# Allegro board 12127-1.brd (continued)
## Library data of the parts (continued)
C194 = C402H22: tolerance: 78.15322.2FL
C195 C3321 = C402H22: tolerance: 78.10521.5FL
C199 = C402H22: tolerance: 78.33224.2FL
C201 C204 C241 PC69 = C603H36: tolerance: 78.10422.2BL
C208 = C402H22: tolerance: 78.15134.1FL
C209 C3310-C3312 = C402H22: tolerance: 78.22321.2FL
C229 = C603H36: tolerance: 78.10523.2BL
C235 C236 C239 = C603: tolerance: 78.22224.2BL
C378 C379 = C402H24: tolerance: 78.12034.1FL
C383 = C402H22: tolerance: 78.47423.5FL; signal model: C402H20_SCD1U10V2KX-4GP
C423 = C603H36: tolerance: 78.12034.1BL
C443 = C603H36: tolerance: 78.15034.1BL
C467 C477 C518 C536 = C603H36: tolerance: 78.10613.5BL
C484 UC103 = C603H36: tolerance: 78.10523.5BL
C538 C539 = C402H22: tolerance: 78.10423.2FL; signal model: C402H22_SCD01U16V2KX-3GP
CMCLR1 MECLR1 PWCLR1 = 21S-91-03GB01: tolerance: 21.61445.103
D1 = SOT23-2D4-312H44: tolerance: 75.00054.I7D
D2 = SOD523AKH28: tolerance: 83.02015.0AF
D8 D18 = SOD323AKH38: tolerance: 83.00355.D1F
D21 D37 = SOD323AKH42: tolerance: 83.04148.D1H
D23 D26 = SOT23-2D4-312H48: tolerance: 75.00040.A7D
DB1 = G800W306018EU: tolerance: 21.61925.102
DIMM1 DIMM2 = 78079-0001: tolerance: 22.10244.D61
DQ61 Q12 Q44 Q45 Q53 Q57 Q59-Q61 Q70-Q72 Q74 Q79 Q109 Q110 = SOT23CBE2D4H44: tolerance: 84.T3904.C11
F5 F8 = POLYSW-4633-UH24: tolerance: 69.50007.B81
F6 F7 F9 F17 F18 = POLYSW-3217-UH40: tolerance: 69.50007.B91
FL1-FL5 L1 L2 L14-L16 L21 = L402H24: tolerance: 68.00213.031
FNCPU1 = HF08040-M1: tolerance: 21.60641.104
FVS1 = TPAD385X385: tolerance: ZZ.00PAD.Y31
G1 G2 G8-G11 = CON2C-U: tolerance: ZZ.CON2C.XXX
G3-G7 = GAP-CLOSE-PWR: tolerance: ZZ.CON2d.XXX
H1-H6 = GENS315R158-8-F-A: tolerance: ZZ.SCREW.541
H7 = STF256R107H132: tolerance: 34.3KF01.001
HDMI1 = G3168-18000101-00: tolerance: 62.10078.531
L3 R173 R178 R184-R187 R280 R281 R290 R532 R548 R567 = 0R0805-PAD: tolerance: ZZ.R0805.ZZZ
L4 = L201209H44: tolerance: 68.00029.191
L5-L7 L11-L13 L17 L20 = L1608-UH38: tolerance: 68.00217.361; signal model: L1608-UH38_FCM1608CF-750T2-GP
L8 = L603H38: tolerance: 68.00335.181
L18 L19 L22 L24 L32 L51 = L125100-4P-3H27: tolerance: 68.01210.20I
L23 = L3330-1230H95: tolerance: 68.4R710.20S
L27 L39 L40 = RT-D6-4D5-1010H375: tolerance: 19.40346.101
L44 = L603H38: tolerance: 68.00909.101
L45 = RT-D6D5-13H414-U: tolerance: 19.40364.001
L50 = RT-D6D2-108108H426: tolerance: 19.40346.051
LED1 = 19-21UBC-1: tolerance: 83.01921.C70
LEDH1 = 14452190: tolerance: 21.62711.206
LPC1 = A2005WV0-2DX7P-6T-2D3: tolerance: 21.61154.207
MINI1 = 80051-6021: tolerance: 20.F1692.052
PC73 = C603: tolerance: 78.15224.2BL
PR83 PR110 PR111 PR127 R87 R182 R248 R259 R266 R267 R270 R293 = R805H24: tolerance: 63.2R231.16L
PR84 = R402H16: tolerance: 64.47035.6DL
PR85 R79 R209 R241 R254-R256 R283 R302 R682 R684 R693 R703 R729 R738 = R402H16: tolerance: 64.10025.6DL
PR86 R200 R229 R243 R305 R429 R472 R677 R678 R681 R689-R692 R699 R705 = R402H16: tolerance: 63.R0034.1DL
PR87 = R402H16: tolerance: 64.11525.6DL
PR106 PR134 R41 R106 R114 R115 R240 = R402H16: tolerance: 64.10035.6DL
PR109 PR126 R24 R140 R181 R193 R197 R312 R351 R367 R388 R395 R398 R402 R403 R405 R410 R414 R415 R418-R420 R422 R427 R439 R441 R442 R445 R455 R464-R467 R485 R486 R491 R508 R524 R534 R536 R556 R560 R562-R566 R570 R571 R573 R574 R580 R583-R585 R590 R593-R597 R602 R605-R607 R609 R613 R615 R616 R619-R621 R623 R625 R634 R636 R642 R647 R648 R650 R651 R658 R659 R662 R669 R670 R672 R676 R679 R683 R685 R687 R688 R698 R707 R712 R713 R755 R762 R776-R778 R788 R789 R791 R794 R795 R2239 UR98-UR100 UR118 = R402H16: tolerance: 63.10334.1DL
PU8 = DFN10G3-G265175H32: tolerance: 74.08237.B73
Q4 Q5 Q58 Q77 Q78 Q80 = SOT23DGS2D4H44: tolerance: 84.2N702.031
Q6 Q39 Q46 Q47 = SOT23DGS2D8H50: tolerance: 84.03413.A31
Q9-Q11 Q14 Q17 = SOT23-2D4-312H46: tolerance: 75.05125.07D
Q13 Q16 Q26 Q27 Q31 Q32 Q34 = PPAK-5PH45: tolerance: 84.00172.A37
Q15 Q22 Q23 Q28-Q30 Q35 Q43 = PPAK-5PH45: tolerance: 84.SRA12.037
Q37 Q40 Q42 Q48-Q50 Q55 Q62 Q64 Q67 QF2 = SOT-363H44: tolerance: 75.03904.B7C
Q38 = SOT23DGS2D4H44: tolerance: 84.2N702.J31
Q51 = SMD-TO-252-DGS6698H99: tolerance: 84.03006.036
Q54 Q56 = SOT23DGS2D4H44: tolerance: 84.27002.W31
Q69 Q73 U3 U4 U53 = SOT-363H44: tolerance: 75.27002.B7C
Q82 = SOT23CBE2D4H44: tolerance: 84.T3906.A11
Q89 Q90 = SOT23DGS2D8H50: tolerance: 84.03401.B31
Q108 = SOT-363H44: tolerance: 84.M3904.B1F
R3 R4 R21 R70 R82 R84 R88 R144 R257 R392 R411 R413 R423 R456-R458 R469 R476 R477 R484 R504 R507 R514 R519 R525 R538 R577 R598 R599 R601 R618 R624 R627 R630 R631 R635 R646 R649 R655 R656 R660 R696 R701 R717 R737 R754 R756 R757 R767 R773 R790 R792 R810 R826-R846 R848 R849 R865 R867 = R402H16: tolerance: 63.10234.1DL
R5 R12 R20 R67 R68 R356 R404 R459 R481 R499 R765 = R402H16: tolerance: 64.20025.6DL
R6 R7 R43 R44 R77 R90 R92 R130 R495 R2220 = R402H16: tolerance: 63.22334.1DL
R8 R261 R2240 = R402H16: tolerance: 64.39225.6DL
R9 R10 R15-R18 R45 R50 R51 R65 R66 R183 R362 R526 R535 R546 = R402H16: tolerance: 63.22234.1DL
R11 R110 R117 R282 R284 = 0R0603-PAD-1: tolerance: ZZ.00PAD.M21
R13 R14 R111 R119 R541 R680 R764 R796 R812 R818 R2219 = R402H14: tolerance: 64.10005.6DL
R19 R710 = R402H16: tolerance: 64.20015.6DL
R25 R73 R2234-R2236 = R402H16: tolerance: 63.51234.1DL
R26 R48 R52 R53 R76 R91 R417 R424 = R402H16: tolerance: 64.75R05.6DL
R27 R49 R72 R83 R107 R352 R438 R470 R492 R498 R604 R638 R671 R709 R727 R736 R760 R2237 = R402H16: tolerance: 63.47234.1DL
R29 R69 R171 = R603H22: tolerance: 63.00000.00L
R30-R32 R159 R412 R425 R426 = R402H16: tolerance: 64.15005.6DL
R33 R34 = R402H16: tolerance: 64.49905.6DL
R57-R64 = R402H16: tolerance: 63.47134.1DL
R71 R112 R124 R132 R139 R198 R242 R258 R269 R304 R311 R333 R497 R552 R578 R579 R667 R673 R759 R806-R808 R823 R824 R847 R1248 = R402H16: tolerance: 63.R0034.1DL; signal model: R402H16_0R2J-2-GP
R74 R478 R488 R505 R512 R542 R610 R612 R629 R632 R652 R850 R852 = R402H16: tolerance: 63.33034.1DL
R75 R118 = R402H16: tolerance: 64.47R05.6DL
R78 R298 R299 R502 = R402H16: tolerance: 63.10534.1DL
R80 R97 R99 R104 R409 = 0R0603-PAD: tolerance: ZZ.R0603.001
R93-R95 = R402H16: tolerance: 64.12035.6DL
R96 R98 R100 R287 = R402H14: tolerance: 64.10R05.6DL
R102 R800 = R402H16: tolerance: 64.11005.6DL
R103 = R402H16: tolerance: 64.18025.6DL
R105 = R402H16: tolerance: 64.56225.6DL
R108 R401 = R402H16: tolerance: 63.10434.1DL
R109 = R402H16: tolerance: 64.51R15.6DL
R113 = R402H16: tolerance: 64.75025.6DL
R116 R233 R286 R288 R518 R664 R665 R704 R769 R853 R857 R859 = R402H16: tolerance: 64.10015.6DL
R120 = NTC-402H24: tolerance: 69.60028.031
R126 = R402H16: tolerance: 64.47R55.6DL
R127-R129 R136 R138 R264 R416 R533 R561 R581 R637 R702 R708 R761 R819-R821 = 0R0402-PAD: tolerance: ZZ.R0402.001; signal model: R402H16_0R2J-2-GP
R131 = R402H16: tolerance: 63.10334.1DL; signal model: R402H16_0R2J-2-GP
R133 R358 R368 R369 R399 R468 R471 R643 R751 R752 R2243 = R402H16: tolerance: 64.82015.6DL
R134 = R402H16: tolerance: 63.82234.1DL
R145 R428 R723 UC97 UR106 UR107 UR119 = R402H16: tolerance: 63.15334.1DL
R150 R391 R851 R854 R858 = 0R0402-PAD: tolerance: ZZ.R0402.001
R153 R396 R406-R408 R421 = R402H16: tolerance: 63.22034.1DL
R156 R177 R203 R340 R639 R640 R661 R663 R816 R2216 = R402H16: tolerance: 64.51R05.6DL
R162 R430 = R603H22: tolerance: 64.10045.55L
R163-R165 = R402H16: tolerance: 64.68015.6DL
R172 = R402H16: tolerance: 64.24915.6DL
R180 R190 R195 R196 R245 R268 = R805H24: tolerance: 63.1R031.16L
R207 = NTC-603H28: tolerance: 69.60026.091
R212 R400 = R402H16: tolerance: 64.39015.6DL
R219 = R402H16: tolerance: 64.20525.6DL
R220 = R402H16: tolerance: 64.56035.6DL
R221 = R402H16: tolerance: 64.69825.6DL
R222 = R402H16: tolerance: 64.88715.6DL
R225 = R402H16: tolerance: 64.59025.6DL
R226 = R402H16: tolerance: 64.54R95.6DL
R231 = R402H16: tolerance: 64.31625.6DL
R235 = R402H16: tolerance: 64.19635.6DL
R239 = R402H16: tolerance: 64.68025.6DL
R251 = R805H24: tolerance: 63.10133.16L
R263 = R402H16: tolerance: 63.56034.1DL
R265 R855 R863 = R402H16: tolerance: 64.2R005.6DL
R277 R2226 = R402H16: tolerance: 64.33015.6DL
R279 = R402H16: tolerance: 64.12425.6DL
R307 R793 R805 R856 R864 = R402H16: tolerance: 64.24R95.6DL
R341 R360 R554 = R402H14: tolerance: 63.10134.1DL
R353 R482 = R402H16: tolerance: 64.90R95.6DL
R357 R483 R489 R493 R496 R521 R523 R866 = 0R0402-PAD-1: tolerance: ZZ.00PAD.M11
R393 = R402H16: tolerance: 64.64905.6DL
R494 R515 = R402H16: tolerance: 63.39434.1DL
R516 = R402H16: tolerance: 64.44R25.6DL
R537 = R402H16: tolerance: 64.12405.6DL
R547 R576 R694 R695 R697 = R402H16: tolerance: 64.75015.6DLDL
R549 R644 R734 = R805H24: tolerance: 63.22133.16L
R550 R551 R555 = R805H24: tolerance: 63.R0031.16L
R553 = R603H22: tolerance: 63.10633.15L
R559 = R402H16: tolerance: 64.21005.6DL
R568 R600 R666 R674 R720 R733 R774 R775 SR732 = 0R0402-PAD: tolerance: ZZ.R0402.ZZZ
R572 R668 = R402H16: tolerance: 63.20334.1DL
R617 = R402H16: tolerance: 64.22R65.6DL
R633 R641 R657 = R402H16: tolerance: 63.68134.1DL
R653 R654 = R603H22: tolerance: 63.75033.15L
R711 = R402H16: tolerance: 64.21015.6DL
R722 = R603H22: tolerance: 63.10233.15L
R730 R768 = R402H16: tolerance: 63.27234.1DL
R739 = R402H16: tolerance: 64.49915.6DL
R747 = R402H16: tolerance: 63.56234.1DL
R766 R811 R817 = R402H16: tolerance: 64.20005.6DL
R772 = 0R0805-PAD: tolerance: ZZ.R0805.001
R797-R799 R804 = R402H16: tolerance: 64.49R95.6DL
R1549 = R402H16: tolerance: 63.47334.1DL
R2215 = R402H16: tolerance: 64.15015.6DL
R2217 = R402H16: tolerance: 64.82505.6DL
R2218 UR108 UR109 = R402H16: tolerance: 64.24905.6DL
R2225 = R402H16: tolerance: 64.5R115.6DL
R2227 = R402H16: tolerance: 64.18015.6DL
R2230 = R402H16: tolerance: 64.60415.6DL
R2231 = R402H16: tolerance: 64.26715.6DL
R2233 = R402H16: tolerance: 64.11825.6DL
R2238 = R402H16: tolerance: 63.30334.1DL
R2246 = R603H22: tolerance: 63.2R233.15L
RJ45 = RU4-161A9WGF: tolerance: 22.10321.K21
RN2 RN3 RN7 = ARES8-CN24H20: tolerance: 66.82236.A8L
RN22 = SMD-ARES4H18: tolerance: 66.10236.04L
RN31-RN36 RN40-RN42 RN64 RN66 = ARES2H18: tolerance: 66.10336.04L
RN46 = ARES8-CN24-UH20: tolerance: 66.33036.A8L
RN57 RN58 RN60 RN62 = SMD-ARES4H18: tolerance: 66.33036.04L
RN65 = SMD-ARES4: tolerance: 66.82236.04L
SATA0 = ABA-SAT-010-K50: tolerance: 20.81696.007
SATA1 = ABA-SAT-010-K04-U: tolerance: 20.81274.007
SLOT1 = 1-1470780-7: tolerance: 20.50222.036
SLOT2 = 4-1470780-7: tolerance: 20.50232.164
TC1-TC3 TC10 TC12 TC29 TC41 = ECAP-100D6D3H375: tolerance: 09.56710.A8L
TC4-TC7 = ECAP-100D6D3H237: tolerance: 09.1071D.2AL
TC9 TC34 TC40 = ECAP-138D8-UH355: tolerance: 09.2771D.C8L
TC11 = ECAP-138D8H512: tolerance: 09.4771D.L16
TC13 = ECAP-80D5H493: tolerance: 09.1071D.A89
TC15 TC22 TC42 TC45 = ECAP-100D6D3H375: tolerance: 09.8271V.08L
TC38 UTC5-UTC7 UTC9 = ECAP-100D6D3H473: tolerance: 09.2271D.X8L
TP1 TP3-TP7 TP10 TP32-TP36 TP40-TP42 TP48-TP51 TP53 TP56 TP66-TP68 TP76-TP80 TP85 TP86 TP88 TP90 = TPAD24: tolerance: ZZ.PAD24.001
TP2 TP87 TP103-TP105 TP107-TP113 TP116-TP131 TP133-TP169 = TPAD28: tolerance: ZZ.PAD28.XXX
TR1-TR4 = L2012-4P-MH56: tolerance: 69.10171.001
TR9-TR14 TR18-TR20 TR22-TR27 = L125100-4P-1H37: tolerance: 68.01012.201
U1 U6 U9 U11 U24 U26 UU12 UU37 UU38 UU42 UU43 = SOT-6H58: tolerance: 75.09904.07C
U2 = LQFP48H63: tolerance: 71.00662.A0G
U8 U16 U18 = DFN8G2-G1309-UH40: tolerance: 74.81161.073
U10 U15 U47 = SLP2510P8-1H22: tolerance: 83.03010.0A0
U12 = QFN32J4-G2D9-U1H36: tolerance: 71.08111.U03
U13 = SOIC8-G3530H63: tolerance: 74.05337.031
U14 U31 = SOIC8H79: tolerance: 84.02402.037
U17 = SOT-6H58: tolerance: 74.05611.03P
U22 = TSOIC28-3H44: tolerance: 71.08172.00W
U23 = TSOIC28H48: tolerance: 71.03324.H0W
U25 U32 U34 = DFN10G2510H26: tolerance: 83.01045.AA0
U27 = SKTBGA1150R740611UH367NF: tolerance: 62.10055.741
U29 = BGA708Z2322H65: tolerance: 71.0LYNX.B0U
U30CN1 U35CN1 = ACA-SPI-004-K-U: tolerance: 62.10089.001
U33 U39 = SOIC8-1H86: tolerance: 72.25640.D01
U36 = SMD-TO-252-4H94: tolerance: 74.01085.P3M
U51 = SOIC8-G3530H63: tolerance: 74.05930.B3D
U52 = QFN32J4-G2D8-3H40: tolerance: 74.81102.C73
U61 = LQFP64H63: tolerance: 71.08772.B0G
UR112 = R402H16: tolerance: 63.33134.1DL
USB3R1 = SKT-USB22-156174: tolerance: 22.10339.641
USBCN1 = SKT-USB12-157183: tolerance: 22.10321.W41
USBF1 USBF2 = 210-92-05GB04: tolerance: 21.62876.205
USBF3 = ABA-USB-050-K07: tolerance: 22.10341.131
VGA1 = DZ11AA1-H5W7-4F: tolerance: 20.20503.015
X1 X2 = SMD49-4H56: tolerance: 82.30020.851
X3 = SMD49-6914-0403H56: tolerance: 82.30001.841
XDPC1 = BSH-03001-FDA: tolerance: 20.F0441.060

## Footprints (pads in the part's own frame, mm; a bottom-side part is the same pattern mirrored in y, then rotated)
0R0402-PAD
  custom 0.14x0.14 smd: 1(0,0.445) 2(0,-0.445)
0R0402-PAD-1
  custom 0.14x0.14 smd: 1(0,0.445) 2(0,-0.445)
0R0603-PAD
  custom 0.216x0.216 smd: 1(0,0.851) 2(0,-0.673)
0R0603-PAD-1
  custom 0.216x0.216 smd: 1(0,0.851) 2(0,-0.673)
0R0805-PAD
  rect 1.397x1.562 smd: 1(0,0.965)
  rect 1.397x1.569 smd: 2(0,-0.965)
1-1470780-7
  round 0.254 hole 2.362 unplated: (0,0) (9.149,0)
  round 1.092 hole 0.737: A1(-11.651,1.25) A2(-10.65,3.25) A3(-9.651,1.25) A4(-8.65,3.25) A5(-7.65,1.25) A6(-6.651,3.25) A7(-5.65,1.25) A8(-4.651,3.25) A9(-3.65,1.25) A10(-2.65,3.25) A11(-1.651,1.25) A12(1.35,3.25) A13(2.349,1.25) A14(3.349,3.25) A15(4.35,1.25) A16(5.349,3.25) A17(6.35,1.25) A18(7.349,3.25) B1(-11.651,-1.25) B2(-10.65,-3.25) B3(-9.651,-1.25) B4(-8.65,-3.25) B5(-7.65,-1.25) B6(-6.651,-3.25) B7(-5.65,-1.25) B8(-4.651,-3.25) B9(-3.65,-1.25) B10(-2.65,-3.25) B11(-1.651,-1.25) B12(1.35,-3.25) B13(2.349,-1.25) B14(3.349,-3.25) B15(4.35,-1.25) B16(5.349,-3.25) B17(6.35,-1.25) B18(7.349,-3.25)
1-1775099-0
  round 2.159 hole 1.397: 1(-2.101,2.75) 2(2.101,2.75) 3(-2.101,-2.75) 4(2.101,-2.75)
4-1470780-7
  round 0.254 hole 2.362 unplated: (0,0) (73.149,0)
  round 1.092 hole 0.737: A1(-11.65,1.25) A2(-10.65,3.25) A3(-9.649,1.25) A4(-8.65,3.25) A5(-7.65,1.25) A6(-6.65,3.25) A7(-5.65,1.25) A8(-4.649,3.25) A9(-3.65,1.25) A10(-2.65,3.25) A11(-1.65,1.25) A12(1.35,3.25) A13(2.349,1.25) A14(3.35,3.25) A15(4.35,1.25) A16(5.351,3.25) A17(6.35,1.25) A18(7.349,3.25) A19(8.35,1.25) A20(9.35,3.25) A21(10.351,1.25) A22(11.35,3.25) A23(12.349,1.25) A24(13.35,3.25) A25(14.35,1.25) A26(15.35,3.25) A27(16.35,1.25) A28(17.349,3.25) A29(18.35,1.25) A30(19.35,3.25) A31(20.35,1.25) A32(21.35,3.25) A33(22.349,1.25) A34(23.35,3.25) A35(24.35,1.25) A36(25.35,3.25) A37(26.35,1.25) A38(27.349,3.25) A39(28.35,1.25) A40(29.35,3.25) A41(30.35,1.25) A42(31.35,3.25) A43(32.349,1.25) A44(33.35,3.25) A45(34.35,1.25) A46(35.35,3.25) A47(36.35,1.25) A48(37.349,3.25) A49(38.35,1.25) A50(39.35,3.25) A51(40.35,1.25) A52(41.35,3.25) A53(42.349,1.25) A54(43.35,3.25) A55(44.35,1.25) A56(45.35,3.25) A57(46.35,1.25) A58(47.349,3.25) A59(48.35,1.25) A60(49.35,3.25) A61(50.35,1.25) A62(51.35,3.25) A63(52.349,1.25) A64(53.35,3.25) A65(54.35,1.25) A66(55.35,3.25) A67(56.35,1.25) A68(57.349,3.25) A69(58.35,1.25) A70(59.35,3.25) A71(60.35,1.25) A72(61.35,3.25) A73(62.349,1.25) A74(63.35,3.25) A75(64.35,1.25) A76(65.35,3.25) A77(66.35,1.25) A78(67.349,3.25) A79(68.35,1.25) A80(69.35,3.25) A81(70.35,1.25) A82(71.35,3.25) B1(-11.65,-1.25) B2(-10.65,-3.25) B3(-9.649,-1.25) B4(-8.65,-3.25) B5(-7.65,-1.25) B6(-6.65,-3.25) B7(-5.65,-1.25) B8(-4.649,-3.25) B9(-3.65,-1.25) B10(-2.65,-3.25) B11(-1.65,-1.25) B12(1.35,-3.25) B13(2.349,-1.25) B14(3.35,-3.25) B15(4.35,-1.25) B16(5.351,-3.25) B17(6.35,-1.25) B18(7.349,-3.25) B19(8.35,-1.25) B20(9.35,-3.25) B21(10.351,-1.25) B22(11.35,-3.25) B23(12.349,-1.25) B24(13.35,-3.25) B25(14.35,-1.25) B26(15.35,-3.25) B27(16.35,-1.25) B28(17.349,-3.25) B29(18.35,-1.25) B30(19.35,-3.25) B31(20.35,-1.25) B32(21.35,-3.25) B33(22.349,-1.25) B34(23.35,-3.25) B35(24.35,-1.25) B36(25.35,-3.25) B37(26.35,-1.25) B38(27.349,-3.25) B39(28.35,-1.25) B40(29.35,-3.25) B41(30.35,-1.25) B42(31.35,-3.25) B43(32.349,-1.25) B44(33.35,-3.25) B45(34.35,-1.25) B46(35.35,-3.25) B47(36.35,-1.25) B48(37.349,-3.25) B49(38.35,-1.25) B50(39.35,-3.25) B51(40.35,-1.25) B52(41.35,-3.25) B53(42.349,-1.25) B54(43.35,-3.25) B55(44.35,-1.25) B56(45.35,-3.25) B57(46.35,-1.25) B58(47.349,-3.25) B59(48.35,-1.25) B60(49.35,-3.25) B61(50.35,-1.25) B62(51.35,-3.25) B63(52.349,-1.25) B64(53.35,-3.25) B65(54.35,-1.25) B66(55.35,-3.25) B67(56.35,-1.25) B68(57.349,-3.25) B69(58.35,-1.25) B70(59.35,-3.25) B71(60.35,-1.25) B72(61.35,-3.25) B73(62.349,-1.25) B74(63.35,-3.25) B75(64.35,-1.25) B76(65.35,-3.25) B77(66.35,-1.25) B78(67.349,-3.25) B79(68.35,-1.25) B80(69.35,-3.25) B81(70.35,-1.25) B82(71.35,-3.25)
19-21UBC-1
  rect 0.94x1.067 smd: 1(-0.711,0) 2(0.711,0)
21S-91-03GB01
  round 1.422 hole 1.016: 1(-2.54,0) 2(0,0) 3(2.54,0)
210-92-05GB04
  round 1.422 hole 1.016: 1(-5.08,-1.27) 2(-5.08,1.27) 3(-2.54,-1.27) 4(-2.54,1.27) 5(0,-1.27) 6(0,1.27) 7(2.54,-1.27) 8(2.54,1.27) 10(5.08,1.27)
  rect 0.025x0.025 smd: 9(5.08,-1.27)
78079-0001
  round 0.254 hole 2.464 unplated: (-57,0) (81,0)
  round 0.254 hole 2.464x1.803 unplated: (0,0)
  round 1.092 hole 0.737: 1(-49.5,-0.95) 2(-48.5,-2.85) 3(-47.5,-0.95) 4(-46.5,-2.85) 5(-45.5,-0.95) 6(-44.5,-2.85) 7(-43.5,-0.95) 8(-42.5,-2.85) 9(-41.5,-0.95) 10(-40.5,-2.85) 11(-39.5,-0.95) 12(-38.5,-2.85) 13(-37.5,-0.95) 14(-36.5,-2.85) 15(-35.5,-0.95) 16(-34.5,-2.85) 17(-33.5,-0.95) 18(-32.5,-2.85) 19(-31.5,-0.95) 20(-30.5,-2.85) 21(-29.5,-0.95) 22(-28.5,-2.85) 23(-27.5,-0.95) 24(-26.5,-2.85) 25(-25.5,-0.95) 26(-24.5,-2.85) 27(-23.5,-0.95) 28(-22.5,-2.85) 29(-21.5,-0.95) 30(-20.5,-2.85) 31(-19.5,-0.95) 32(-18.5,-2.85) 33(-17.5,-0.95) 34(-16.5,-2.85) 35(-15.5,-0.95) 36(-14.5,-2.85) 37(-13.5,-0.95) 38(-12.5,-2.85) 39(-11.5,-0.95) 40(-10.5,-2.85) 41(-9.5,-0.95) 42(-8.5,-2.85) 43(-7.5,-0.95) 44(-6.5,-2.85) 45(-5.5,-0.95) 46(-4.5,-2.85) 47(-3.5,-0.95) 48(-2.5,-2.85) 49(2.5,-0.95) 50(3.5,-2.85) 51(4.5,-0.95) 52(5.5,-2.85) 53(6.5,-0.95) 54(7.5,-2.85) 55(8.5,-0.95) 56(9.5,-2.85) 57(10.5,-0.95) 58(11.5,-2.85) 59(12.5,-0.95) 60(13.5,-2.85) 61(14.5,-0.95) 62(15.5,-2.85) 63(16.5,-0.95) 64(17.5,-2.85) 65(18.5,-0.95) 66(19.5,-2.85) 67(20.5,-0.95) 68(21.5,-2.85) 69(22.5,-0.95) 70(23.5,-2.85) 71(24.5,-0.95) 72(25.5,-2.85) 73(26.5,-0.95) 74(27.5,-2.85) 75(28.5,-0.95) 76(29.5,-2.85) 77(30.5,-0.95) 78(31.5,-2.85) 79(32.5,-0.95) 80(33.5,-2.85) 81(34.5,-0.95) 82(35.5,-2.85) 83(36.5,-0.95) 84(37.5,-2.85) 85(38.5,-0.95) 86(39.5,-2.85) 87(40.5,-0.95) 88(41.5,-2.85) 89(42.5,-0.95) 90(43.5,-2.85) 91(44.5,-0.95) 92(45.5,-2.85) 93(46.5,-0.95) 94(47.5,-2.85) 95(48.5,-0.95) 96(49.5,-2.85) 97(50.5,-0.95) 98(51.5,-2.85) 99(52.5,-0.95) 100(53.5,-2.85) 101(54.5,-0.95) 102(55.5,-2.85) 103(56.5,-0.95) 104(57.5,-2.85) 105(58.5,-0.95) 106(59.5,-2.85) 107(60.5,-0.95) 108(61.5,-2.85) 109(62.5,-0.95) 110(63.5,-2.85) 111(64.5,-0.95) 112(65.5,-2.85) 113(66.5,-0.95) 114(67.5,-2.85) 115(68.5,-0.95) 116(69.5,-2.85) 117(70.5,-0.95) 118(71.5,-2.85) 119(72.5,-0.95) 120(73.5,-2.85) 121(-49.5,2.85) 122(-48.5,0.95) 123(-47.5,2.85) 124(-46.5,0.95) 125(-45.5,2.85) 126(-44.5,0.95) 127(-43.5,2.85) 128(-42.5,0.95) 129(-41.5,2.85) 130(-40.5,0.95) 131(-39.5,2.85) 132(-38.5,0.95) 133(-37.5,2.85) 134(-36.5,0.95) 135(-35.5,2.85) 136(-34.5,0.95) 137(-33.5,2.85) 138(-32.5,0.95) 139(-31.5,2.85) 140(-30.5,0.95) 141(-29.5,2.85) 142(-28.5,0.95) 143(-27.5,2.85) 144(-26.5,0.95) 145(-25.5,2.85) 146(-24.5,0.95) 147(-23.5,2.85) 148(-22.5,0.95) 149(-21.5,2.85) 150(-20.5,0.95) 151(-19.5,2.85) 152(-18.5,0.95) 153(-17.5,2.85) 154(-16.5,0.95) 155(-15.5,2.85) 156(-14.5,0.95) 157(-13.5,2.85) 158(-12.5,0.95) 159(-11.5,2.85) 160(-10.5,0.95) 161(-9.5,2.85) 162(-8.5,0.95) 163(-7.5,2.85) 164(-6.5,0.95) 165(-5.5,2.85) 166(-4.5,0.95) 167(-3.5,2.85) 168(-2.5,0.95) 169(2.5,2.85) 170(3.5,0.95) 171(4.5,2.85) 172(5.5,0.95) 173(6.5,2.85) 174(7.5,0.95) 175(8.5,2.85) 176(9.5,0.95) 177(10.5,2.85) 178(11.5,0.95) 179(12.5,2.85) 180(13.5,0.95) 181(14.5,2.85) 182(15.5,0.95) 183(16.5,2.85) 184(17.5,0.95) 185(18.5,2.85) 186(19.5,0.95) 187(20.5,2.85) 188(21.5,0.95) 189(22.5,2.85) 190(23.5,0.95) 191(24.5,2.85) 192(25.5,0.95) 193(26.5,2.85) 194(27.5,0.95) 195(28.5,2.85) 196(29.5,0.95) 197(30.5,2.85) 198(31.5,0.95) 199(32.5,2.85) 200(33.5,0.95) 201(34.5,2.85) 202(35.5,0.95) 203(36.5,2.85) 204(37.5,0.95) 205(38.5,2.85) 206(39.5,0.95) 207(40.5,2.85) 208(41.5,0.95) 209(42.5,2.85) 210(43.5,0.95) 211(44.5,2.85) 212(45.5,0.95) 213(46.5,2.85) 214(47.5,0.95) 215(48.5,2.85) 216(49.5,0.95) 217(50.5,2.85) 218(51.5,0.95) 219(52.5,2.85) 220(53.5,0.95) 221(54.5,2.85) 222(55.5,0.95) 223(56.5,2.85) 224(57.5,0.95) 225(58.5,2.85) 226(59.5,0.95) 227(60.5,2.85) 228(61.5,0.95) 229(62.5,2.85) 230(63.5,0.95) 231(64.5,2.85) 232(65.5,0.95) 233(66.5,2.85) 234(67.5,0.95) 235(68.5,2.85) 236(69.5,0.95) 237(70.5,2.85) 238(71.5,0.95) 239(72.5,2.85) 240(73.5,0.95)
80051-6021
  round 0.254 hole 1.575 unplated: (-12.5,0)
  round 0.254 hole 1.067 unplated: (12.5,0)
  rect 0.559x2.007 smd: 1(-11.8,-4.097) 2(-11.4,4.097) 3(-11,-4.097) 4(-10.6,4.097) 5(-10.2,-4.097) 6(-9.8,4.1) 7(-9.4,-4.097) 8(-9,4.097) 9(-8.6,-4.097) 10(-8.2,4.097) 11(-7.8,-4.097) 12(-7.4,4.097) 13(-7,-4.097) 14(-6.6,4.097) 15(-6.2,-4.097) 16(-5.8,4.097) 17(-2.2,-4.097) 18(-1.8,4.097) 19(-1.4,-4.097) 20(-1,4.097) 21(-0.6,-4.097) 22(-0.2,4.097) 23(0.2,-4.097) 24(0.6,4.097) 25(1,-4.097) 26(1.4,4.097) 27(1.8,-4.097) 28(2.2,4.097) 29(2.6,-4.097) 30(3,4.097) 31(3.4,-4.097) 32(3.8,4.097) 33(4.2,-4.097) 34(4.6,4.097) 35(5,-4.097) 36(5.4,4.097) 37(5.8,-4.097) 38(6.2,4.097) 39(6.6,-4.097) 40(7,4.097) 41(7.4,-4.097) 42(7.8,4.097) 43(8.2,-4.097) 44(8.6,4.097) 45(9,-4.097) 46(9.4,4.097) 47(9.8,-4.097) 48(10.2,4.097) 49(10.6,-4.097) 50(11,4.097) 51(11.4,-4.097) 52(11.8,4.097)
  rect 2.311x3.2 smd: 53(-14.65,-3.5) 54(14.65,-3.5)
14452190
  round 1.397 hole 0.991: 1(6.35,1.27) 2(6.35,-1.27) 3(3.81,1.27) 4(3.81,-1.27) 5(1.27,1.27) 6(1.27,-1.27) 7(-1.27,1.27) 8(-1.27,-1.27) 9(-3.81,1.27) 11(-6.35,1.27) 12(-6.35,-1.27)
  rect 0.025x0.025 smd: 10(-3.81,-1.27)
A2005WV0-2DX7P-6T-2D3
  round 1.27 hole 0.889: 1(-6,-1) 2(-6,1) 3(-4,-1) 4(-4,1) 5(-2,-1) 6(-2,1) 7(0,-1) 8(0,1) 9(2,-1) 10(2,1) 11(4,-1) 12(4,1) 13(6,-1) 14(6,1)
AAA-BAT-029-P02
  round 1.524 hole 1.118: 1(12.29,0)
  round 1.422 hole 1.016: 2(-7.71,0)
ABA-JAK-028-K03
  round 0.254 hole 2.311 unplated: (0,0)
  round 1.422 hole 1.016: 1(0,-3.8) 2(-5,-3.8) 3(-2.5,-3.8) 4(2.5,-3.8) 5(5,-3.8) 22(-3.75,-8.8) 23(-1.25,-8.8) 24(1.25,-8.8) 25(3.75,-8.8) 32(-3.75,-13.8) 33(-1.25,-13.8) 34(1.25,-13.8) 35(3.75,-13.8)
  round 2.718 hole 2.311: G1(6.04,0) G2(-6.04,0) G3(6.04,-11.3) G4(-6.04,-11.3)
ABA-SAT-010-K04-U
  round 1.118 hole 0.762: 1(-3.81,-0.5) 4(0,-0.5) 7(3.81,-0.5)
  oval 1.041x1.168 hole 0.762: 2(-2.54,0.5) 3(-1.27,0.5) 5(1.27,0.5) 6(2.54,0.5)
  round 1.778 hole 1.372: 8(-6.48,0) 9(6.48,0)
ABA-SAT-010-K50
  round 1.118 hole 0.762: 1(3.81,-0.5) 4(0,-0.5) 7(-3.81,-0.5)
  oval 1.041x1.168 hole 0.762: 2(2.54,0.5) 3(1.27,0.5) 5(-1.27,0.5) 6(-2.54,0.5)
  round 1.778 hole 1.372: 8(6.48,0) 9(-6.48,0)
ABA-USB-050-K07
  round 1.168 hole 0.813: 1(-9,1) 2(-7,1) 3(-5,1) 4(-3,1) 5(-1,1) 6(1,1) 7(3,1) 8(5,1) 9(7,1) 10(9,1) 11(9,-1) 12(7,-1) 13(5,-1) 14(3,-1) 15(1,-1) 16(-1,-1) 17(-3,-1) 18(-5,-1) 19(-7,-1)
  rect 0.025x0.025 smd: 20(-9,-1)
ACA-SPI-004-K-U
  rect 0.508x1.499 smd: 1(1.905,4) 2(0.635,4) 3(-0.635,4) 4(-1.905,4) 5(-1.905,-4) 6(-0.635,-4) 7(0.635,-4) 8(1.905,-4)
ARES2H18
  rect 0.356x0.66 smd: 1(-0.325,-0.599) 2(0.325,-0.599) 3(0.325,0.599) 4(-0.325,0.599)
ARES8-CN24-UH20
  rect 0.61x0.66 smd: 1(-0.9,-0.486) 4(0.9,-0.486) 5(0.9,0.486) 8(-0.9,0.486)
  rect 0.305x0.66 smd: 2(-0.25,-0.486) 3(0.25,-0.486) 6(0.25,0.486) 7(-0.25,0.486)
ARES8-CN24H20
  rect 0.61x0.66 smd: 1(-0.9,-0.486) 4(0.9,-0.486) 5(0.9,0.486) 8(-0.9,0.486)
  rect 0.305x0.66 smd: 2(-0.25,-0.486) 3(0.25,-0.486) 6(0.25,0.486) 7(-0.25,0.486)
BGA708Z2322H65
  round 0.533 smd: A2(-10.171,10.299) A40(10.339,10.299) AV1(-10.799,-9.839) AV41(10.799,-9.839) AW2(-10.339,-10.299) AW40(10.339,-10.299) B1(-10.799,9.672) B41(10.799,9.839)
  round 0.406 smd: A3(-9.521,10.299) A39(9.689,10.299) AU1(-10.799,-9.081) AU41(10.799,-9.189) AV2(-10.171,-9.671) AV40(10.171,-9.671) AW3(-9.689,-10.299) AW39(9.689,-10.299) B2(-10.14,9.639) B40(10.171,9.671) C1(-10.799,9.021) C41(10.799,9.081)
  round 0.381 smd: A4(-8.732,10.299) A7(-7.653,10.314) A9(-6.383,10.314) A12(-5.113,10.314) A31(5.098,10.314) A33(6.369,10.314) A35(7.639,10.314) A38(8.965,10.299) AA6(-8.135,-0.464) AA7(-7.424,-0.464) AA8(-6.713,-0.464) AA10(-6.002,-0.464) AA11(-5.29,-0.464) AA12(-4.579,-0.464) AA14(-3.629,-0.423) AA16(-2.823,-0.423) AA17(-2.016,-0.423) AA19(-1.21,-0.423) AA20(-0.403,-0.423) AA22(0.403,-0.423) AA23(1.21,-0.423) AA25(2.016,-0.423) AA26(2.822,-0.423) AA28(3.629,-0.423) AA30(4.579,-0.464) AA31(5.29,-0.464) AA32(6.002,-0.464) AA34(6.713,-0.464) AA35(7.424,-0.464) AA36(8.135,-0.464) AB14(-3.629,-1.269) AB16(-2.823,-1.269) AB17(-2.016,-1.269) AB19(-1.21,-1.269) AB20(-0.403,-1.269) AB22(0.403,-1.269) AB23(1.21,-1.269) AB25(2.016,-1.269) AB26(2.822,-1.269) AB28(3.629,-1.269) AC6(-8.186,-1.53) AC7(-7.424,-1.53) AC8(-6.713,-1.53) AC10(-6.002,-1.53) AC11(-5.29,-1.53) AC12(-4.579,-1.53) AC30(4.579,-1.53) AC31(5.29,-1.53) AC32(6.002,-1.53) AC34(6.713,-1.53) AC35(7.424,-1.53) AC36(8.186,-1.53) AD14(-3.629,-2.115) AD16(-2.823,-2.115) AD17(-2.016,-2.115) AD19(-1.21,-2.115) AD20(-0.403,-2.115) AD22(0.403,-2.115) AD23(1.21,-2.115) AD25(2.016,-2.115) AD26(2.822,-2.115) AD28(3.629,-2.115) AE6(-8.135,-2.597) AE7(-7.424,-2.597) AE8(-6.713,-2.597) AE10(-6.002,-2.597) AE11(-5.29,-2.597) AE12(-4.64,-2.597) AE30(4.64,-2.597) AE31(5.29,-2.597) AE32(6.002,-2.597) AE34(6.713,-2.597) AE35(7.424,-2.597) AE36(8.135,-2.597) AF14(-3.629,-2.96) AF16(-2.823,-2.96) AF17(-2.016,-2.96) AF19(-1.21,-2.96) AF20(-0.403,-2.96) AF22(0.403,-2.96) AF23(1.21,-2.96) AF25(2.016,-2.96) AF26(2.822,-2.96) AF28(3.629,-2.96) AG6(-8.135,-3.804) AG7(-7.424,-3.804) AG8(-6.713,-3.804) AG10(-6.002,-3.804) AG11(-5.29,-3.804) AG12(-4.579,-3.804) AG30(4.64,-3.804) AG31(5.29,-3.804) AG32(6.002,-3.804) AG34(6.713,-3.804) AG35(7.424,-3.804) AG36(8.135,-3.804) AH14(-3.804,-4.14) AH16(-2.597,-4.14) AH18(-1.53,-4.079) AH20(-0.464,-4.079) AH22(0.464,-4.079) AH24(1.53,-4.079) AH26(2.597,-4.14) AH28(3.804,-4.14) AJ1(-10.814,-5.118) AJ14(-3.804,-4.79) AJ16(-2.597,-4.79) AJ18(-1.53,-4.79) AJ20(-0.464,-4.79) AJ22(0.464,-4.79) AJ24(1.53,-4.79) AJ26(2.597,-4.79) AJ28(3.804,-4.79) AJ31(5.164,-5.016) AK6(-7.828,-5.086) AK8(-7.117,-5.086) AK9(-6.405,-5.086) AK11(-5.086,-5.133) AK14(-3.804,-5.502) AK16(-2.597,-5.502) AK18(-1.53,-5.502) AK20(-0.464,-5.502) AK22(0.464,-5.502) AK24(1.53,-5.502) AK26(2.597,-5.502) AK28(3.804,-5.502) AK33(6.344,-5.086) AK34(7.056,-5.086) AK36(7.818,-5.086) AK41(10.814,-5.288) AL11(-5.086,-5.845) AL31(5.086,-5.906) AM1(-10.814,-6.388) AM6(-8.135,-6.179) AM7(-7.485,-6.179) AM8(-6.835,-6.179) AM9(-6.189,-6.335) AM11(-5.086,-6.556) AM14(-3.804,-6.213) AM16(-2.597,-6.213) AM18(-1.53,-6.213) AM20(-0.464,-6.213) AM22(0.464,-6.213) AM24(1.53,-6.213) AM26(2.597,-6.213) AM28(3.804,-6.213) AM31(5.086,-6.617) AM33(6.179,-6.274) AM34(6.835,-6.189) AM35(7.485,-6.189) AM36(8.135,-6.189) AN9(-6.189,-6.985) AN14(-3.804,-6.924) AN16(-2.597,-6.924) AN18(-1.53,-6.924) AN20(-0.464,-6.924) AN22(0.464,-6.924) AN24(1.53,-6.924) AN26(2.597,-6.924) AN28(3.804,-6.924) AN33(6.179,-6.924) AP1(-10.814,-7.658) AP7(-7.332,-7.352) AP9(-6.189,-7.635) AP11(-5.086,-7.318) AP14(-3.804,-7.635) AP16(-2.597,-7.635) AP18(-1.53,-7.686) AP20(-0.464,-7.635) AP22(0.464,-7.635) AP24(1.53,-7.686) AP26(2.597,-7.635) AP28(3.804,-7.635) AP31(5.086,-7.328) AP33(6.179,-7.635) AP35(7.325,-7.347) AR41(10.814,-7.828) AT1(-10.799,-8.357) AT2(-10.148,-8.357) AT40(10.168,-8.357) AT41(10.799,-8.539) AU2(-10.15,-9.021) AU40(10.169,-9.021) AV3(-9.52,-9.671) AV5(-8.34,-9.758) AV39(9.496,-9.671) AW4(-8.965,-10.299) AW7(-7.639,-10.314) AW9(-6.369,-10.314) AW11(-5.099,-10.314) AW30(5.112,-10.314) AW33(6.382,-10.314) AW35(7.652,-10.314) AW38(8.965,-10.299) B3(-9.48,9.639) B37(8.34,9.758) B39(9.52,9.671) C2(-10.14,8.978) C40(10.15,9.021) D1(-10.799,8.371) D2(-10.129,8.327) D40(10.148,8.357) D41(10.799,8.357) E1(-10.814,7.638) F7(-7.325,7.347) F9(-6.179,7.635) F11(-5.086,7.328) F14(-3.804,7.635) F16(-2.597,7.635) F18(-1.53,7.686) F20(-0.464,7.635) F22(0.464,7.635) F24(1.53,7.686) F26(2.597,7.635) F28(3.804,7.635) F31(5.086,7.318) F33(6.189,7.635) F35(7.332,7.352) F41(10.814,7.658) G9(-6.179,6.924) G14(-3.804,6.924) G16(-2.597,6.924) G18(-1.53,6.924) G20(-0.464,6.924) G22(0.464,6.924) G24(1.53,6.924) G26(2.597,6.924) G28(3.804,6.924) G33(6.189,6.985) H1(-10.814,6.558) H6(-8.135,6.189) H7(-7.485,6.189) H8(-6.835,6.189) H9(-6.179,6.274) H11(-5.086,6.617) H14(-3.804,6.213) H16(-2.597,6.213) H18(-1.53,6.213) H20(-0.464,6.213) H22(0.464,6.213) H24(1.53,6.213) H26(2.597,6.213) H28(3.804,6.213) H31(5.086,6.556) H33(6.189,6.335) H34(6.835,6.179) H35(7.485,6.179) H36(8.135,6.179) H41(10.814,6.388) J11(-5.086,5.906) J31(5.086,5.845) K1(-10.814,5.288) K6(-7.818,5.086) K8(-7.056,5.086) K9(-6.344,5.086) K14(-3.804,5.502) K16(-2.597,5.502) K18(-1.53,5.502) K20(-0.464,5.502) K22(0.464,5.502) K24(1.53,5.502) K26(2.597,5.502) K28(3.804,5.502) K31(5.086,5.133) K33(6.405,5.086) K34(7.117,5.086) K36(7.828,5.086) L11(-5.164,5.016) L14(-3.804,4.79) L16(-2.597,4.79) L18(-1.53,4.79) L20(-0.464,4.79) L22(0.464,4.79) L24(1.53,4.79) L26(2.597,4.79) L28(3.804,4.79) M14(-3.804,4.14) M16(-2.597,4.14) M18(-1.53,4.079) M20(-0.464,4.079) M22(0.464,4.079) M24(1.53,4.079) M26(2.597,4.14) M28(3.804,4.14) N6(-8.135,3.804) N7(-7.424,3.804) N8(-6.713,3.804) N10(-6.002,3.804) N11(-5.29,3.804) N12(-4.64,3.804) N30(4.579,3.804) N31(5.29,3.804) N32(6.002,3.804) N34(6.713,3.804) N35(7.424,3.804) N36(8.135,3.804) P14(-3.629,2.96) P16(-2.823,2.96) P17(-2.016,2.96) P19(-1.21,2.96) P20(-0.403,2.96) P22(0.403,2.96) P23(1.21,2.96) P25(2.016,2.96) P26(2.822,2.96) P28(3.629,2.96) R6(-8.135,2.597) R7(-7.424,2.597) R8(-6.713,2.597) R10(-6.002,2.597) R11(-5.29,2.597) R12(-4.64,2.597) R30(4.64,2.597) R31(5.29,2.597) R32(6.002,2.597) R34(6.713,2.597) R35(7.424,2.597) R36(8.135,2.597) T14(-3.629,2.115) T16(-2.823,2.115) T17(-2.016,2.115) T19(-1.21,2.115) T20(-0.403,2.115) T22(0.403,2.115) T23(1.21,2.115) T25(2.016,2.115) T26(2.822,2.115) T28(3.629,2.115) U6(-8.186,1.53) U7(-7.424,1.53) U8(-6.713,1.53) U10(-6.002,1.53) U11(-5.29,1.53) U12(-4.579,1.53) U30(4.579,1.53) U31(5.29,1.53) U32(6.002,1.53) U34(6.713,1.53) U35(7.424,1.53) U36(8.186,1.53) V14(-3.629,1.269) V16(-2.823,1.269) V17(-2.016,1.269) V19(-1.21,1.269) V20(-0.403,1.269) V22(0.403,1.269) V23(1.21,1.269) V25(2.016,1.269) V26(2.822,1.269) V28(3.629,1.269) W6(-8.135,0.464) W7(-7.424,0.464) W8(-6.713,0.464) W10(-6.002,0.464) W11(-5.29,0.464) W12(-4.579,0.464) W14(-3.629,0.423) W16(-2.823,0.423) W17(-2.016,0.423) W19(-1.21,0.423) W20(-0.403,0.423) W22(0.403,0.423) W23(1.21,0.423) W25(2.016,0.423) W26(2.822,0.423) W28(3.629,0.423) W30(4.579,0.464) W31(5.29,0.464) W32(6.002,0.464) W34(6.713,0.464) W35(7.424,0.464) W36(8.135,0.464)
  oval 0.254x0.343 smd: A14(-3.703,10.314) A16(-2.534,10.314) A19(-1.176,10.314) A21(-0.007,10.314) A24(1.352,10.314) A26(2.52,10.314) A28(3.879,10.314) AB4(-8.818,-1.181) AC38(8.818,-1.349) AG4(-8.818,-3.71) AG38(8.818,-3.879) AL5(-8.779,-5.631) AM4(-8.818,-6.28) AM38(8.818,-6.498) AW14(-3.88,-10.314) AW16(-2.521,-10.314) AW18(-1.352,-10.314) AW21(0.007,-10.314) AW23(1.175,-10.314) AW26(2.534,-10.314) AW28(3.702,-10.314) H4(-8.818,6.498) H38(8.818,6.28) J37(8.779,5.631) N4(-8.818,3.879) N38(8.818,3.71) U4(-8.818,1.349) V38(8.818,1.181)
  round 0.305 smd: AA2(-10.306,-0.432) AA3(-9.479,-0.486) AA5(-8.787,-0.491) AA37(8.787,-0.677) AA39(9.479,-0.677) AA40(10.289,-0.677) AB2(-9.916,-1.181) AC2(-10.289,-1.853) AC3(-9.479,-1.853) AC5(-8.779,-1.853) AC40(9.916,-1.349) AD37(8.779,-2.044) AD39(9.479,-2.044) AD40(10.306,-2.098) AE2(-9.87,-2.479) AE4(-9.128,-2.466) AE38(9.128,-2.593) AE40(9.87,-2.581) AF2(-10.306,-2.962) AF3(-9.479,-3.015) AF5(-8.779,-3.015) AF37(8.779,-3.207) AF39(9.479,-3.207) AF40(10.289,-3.207) AG2(-9.916,-3.71) AG40(9.916,-3.823) AH2(-10.212,-4.383) AH3(-9.479,-4.383) AH5(-8.779,-4.383) AJ2(-9.87,-5.009) AJ4(-9.128,-4.995) AJ5(-8.478,-4.968) AJ37(8.779,-4.574) AJ39(9.479,-4.574) AJ40(10.306,-4.58) AK37(8.478,-5.182) AK38(9.128,-5.212) AK40(9.87,-5.208) AL2(-10.306,-5.579) AL3(-9.479,-5.632) AL37(8.779,-5.826) AL39(9.479,-5.826) AL40(10.289,-5.826) AM2(-9.916,-6.327) AM40(9.916,-6.485) AN2(-10.205,-7.009) AN3(-9.479,-6.999) AN4(-8.83,-6.931) AN37(8.779,-7.193) AN39(9.479,-7.193) AN40(10.289,-7.255) AP2(-9.87,-7.626) AP4(-9.132,-7.567) AP5(-8.482,-7.567) AR4(-8.859,-8.157) AR7(-7.684,-7.978) AR11(-5.154,-7.978) AR30(4.968,-7.978) AR35(7.498,-7.978) AR37(8.478,-7.78) AR38(9.128,-7.742) AR39(9.853,-7.738) AT5(-8.283,-8.462) AT7(-7.654,-8.628) AT8(-7.104,-8.279) AT10(-5.737,-8.279) AT11(-5.124,-8.628) AT12(-4.575,-8.279) AT15(-3.208,-8.279) AT16(-2.594,-8.628) AT17(-2.045,-8.279) AT20(-0.678,-8.287) AT21(-0.064,-8.628) AT22(0.49,-8.287) AT24(1.852,-8.279) AT26(2.466,-8.628) AT27(3.015,-8.279) AT29(4.382,-8.279) AT30(4.994,-8.628) AT31(5.545,-8.279) AT34(6.912,-8.279) AT35(7.524,-8.628) AT36(8.115,-8.352) AT38(8.843,-8.357) AU3(-9.496,-9.021) AU5(-8.246,-9.115) AU8(-7.104,-8.979) AU10(-5.737,-8.979) AU12(-4.575,-8.979) AU15(-3.208,-8.979) AU17(-2.045,-8.979) AU20(-0.678,-8.979) AU22(0.485,-8.979) AU24(1.852,-8.979) AU27(3.015,-8.979) AU29(4.382,-8.979) AU31(5.545,-8.979) AU34(6.912,-8.979) AU36(8.115,-9.005) AU39(9.496,-9.021) AV4(-8.908,-9.395) AV7(-7.641,-9.371) AV8(-7.158,-9.806) AV9(-6.409,-9.416) AV10(-5.737,-9.725) AV11(-5.111,-9.371) AV12(-4.628,-9.806) AV14(-3.88,-9.416) AV15(-3.208,-9.789) AV16(-2.581,-9.371) AV17(-2.098,-9.806) AV18(-1.35,-9.416) AV20(-0.678,-9.789) AV21(-0.051,-9.371) AV22(0.432,-9.806) AV23(1.18,-9.416) AV24(1.852,-9.789) AV26(2.479,-9.371) AV27(2.962,-9.806) AV28(3.71,-9.416) AV29(4.382,-9.789) AV30(5.008,-9.351) AV31(5.545,-9.786) AV33(6.303,-9.416) AV34(6.912,-9.789) AV35(7.538,-9.371) AV36(8.113,-9.756) AV38(8.843,-9.652) B4(-8.849,9.457) B6(-8.187,9.781) B7(-7.539,9.371) B8(-6.912,9.789) B9(-6.304,9.416) B11(-5.545,9.786) B12(-5.009,9.351) B13(-4.383,9.789) B14(-3.71,9.416) B15(-2.962,9.806) B16(-2.479,9.371) B18(-1.853,9.789) B19(-1.181,9.416) B20(-0.432,9.806) B21(0.051,9.371) B22(0.677,9.789) B24(1.349,9.416) B25(2.098,9.806) B26(2.581,9.371) B27(3.207,9.789) B28(3.879,9.416) B30(4.627,9.806) B31(5.11,9.371) B32(5.737,9.725) B33(6.409,9.416) B34(7.158,9.806) B35(7.641,9.371) B38(8.908,9.395) C3(-9.48,8.978) C6(-8.187,9.005) C8(-6.912,8.979) C11(-5.545,8.979) C13(-4.383,8.979) C15(-3.015,8.979) C18(-1.853,8.979) C20(-0.486,8.979) C22(0.677,8.979) C25(2.044,8.979) C27(3.207,8.979) C30(4.574,8.979) C32(5.737,8.979) C34(7.104,8.979) C37(8.246,9.115) C39(9.496,9.021) D4(-8.849,8.339) D6(-8.187,8.354) D7(-7.498,8.628) D8(-6.912,8.279) D11(-5.545,8.279) D12(-4.995,8.628) D13(-4.383,8.279) D15(-3.015,8.279) D16(-2.466,8.628) D18(-1.853,8.279) D20(-0.491,8.287) D21(0.064,8.628) D22(0.677,8.287) D25(2.044,8.279) D26(2.593,8.628) D27(3.207,8.279) D30(4.574,8.279) D31(5.123,8.628) D32(5.737,8.279) D34(7.104,8.279) D35(7.654,8.628) D37(8.283,8.462) E3(-9.815,7.752) E4(-9.129,7.752) E5(-8.452,7.752) E7(-7.498,7.978) E12(-4.968,7.978) E31(5.154,7.978) E35(7.684,7.978) E38(8.859,8.157) F37(8.482,7.567) F38(9.132,7.567) F40(9.87,7.626) G2(-10.289,7.255) G3(-9.479,7.19) G5(-8.779,7.19) G38(8.83,6.931) G39(9.479,6.999) G40(10.205,7.009) H2(-9.916,6.485) H40(9.916,6.327) J2(-10.289,5.826) J3(-9.479,5.826) J5(-8.779,5.826) J39(9.479,5.632) J40(10.306,5.579) K2(-9.87,5.208) K4(-9.128,5.212) K5(-8.478,5.182) L2(-10.306,4.58) L3(-9.479,4.574) L5(-8.779,4.574) L37(8.478,4.968) L38(9.128,4.995) L40(9.87,5.009) M37(8.779,4.383) M39(9.479,4.383) M40(10.212,4.383) N2(-9.916,3.823) N40(9.916,3.71) P2(-10.289,3.207) P3(-9.479,3.207) P5(-8.779,3.207) P37(8.779,3.015) P39(9.479,3.015) P40(10.306,2.962) R2(-9.87,2.581) R4(-9.128,2.593) R38(9.128,2.466) R40(9.87,2.479) T2(-10.306,2.098) T3(-9.479,2.044) T5(-8.779,2.044) U2(-9.916,1.349) U37(8.779,1.853) U39(9.479,1.853) U40(10.289,1.853) V40(9.916,1.181) W2(-10.289,0.677) W3(-9.479,0.677) W5(-8.787,0.677) W37(8.787,0.491) W39(9.479,0.486) W40(10.306,0.432) Y2(-9.87,0.051) Y4(-9.128,0.064) Y38(9.128,-0.064) Y40(9.87,-0.051)
  oval 0.343x0.254 smd: AB1(-10.814,-1.181) AC41(10.814,-1.349) AE1(-10.814,-2.54) AE41(10.814,-2.52) AG1(-10.814,-3.708) AG41(10.814,-3.879) AT9(-6.409,-8.319) AT14(-3.88,-8.319) AT18(-1.35,-8.319) AT23(1.18,-8.319) AT28(3.71,-8.319) AT33(6.24,-8.319) D9(-6.24,8.319) D14(-3.71,8.319) D19(-1.181,8.319) D24(1.349,8.319) D28(3.879,8.319) D33(6.409,8.319) N1(-10.814,3.879) N41(10.814,3.708) R1(-10.814,2.52) R41(10.814,2.54) U1(-10.814,1.349) V41(10.814,1.181) Y1(-10.814,-0.01) Y41(10.814,0.01)
  custom 0.083x0.083 smd: AM41(10.814,-6.558) L41(10.814,5.118)
BSH-03001-FDA
  round 0.254 hole 1.016 unplated: (-10.065,0) (10.065,0)
  rect 0.279x2.769 smd: 1(-7.25,-5.526) 2(-7.25,0.198) 3(-6.75,-5.526) 4(-6.75,0.198) 5(-6.25,-5.526) 6(-6.25,0.198) 7(-5.751,-5.526) 8(-5.751,0.198) 9(-5.25,-5.526) 10(-5.25,0.198) 11(-4.75,-5.526) 12(-4.75,0.198) 13(-4.249,-5.526) 14(-4.249,0.198) 15(-3.75,-5.526) 16(-3.75,0.198) 17(-3.25,-5.526) 18(-3.25,0.198) 19(-2.75,-5.526) 20(-2.75,0.198) 21(-2.25,-5.526) 22(-2.25,0.198) 23(-1.75,-5.526) 24(-1.75,0.198) 25(-1.25,-5.526) 26(-1.25,0.198) 27(-0.751,-5.526) 28(-0.751,0.198) 29(-0.25,-5.526) 30(-0.25,0.198) 31(0.25,-5.526) 32(0.25,0.198) 33(0.751,-5.526) 34(0.751,0.198) 35(1.25,-5.526) 36(1.25,0.198) 37(1.75,-5.526) 38(1.75,0.198) 39(2.25,-5.526) 40(2.25,0.198) 41(2.75,-5.526) 42(2.75,0.198) 43(3.25,-5.526) 44(3.25,0.198) 45(3.75,-5.526) 46(3.75,0.198) 47(4.249,-5.526) 48(4.249,0.198) 49(4.75,-5.526) 50(4.75,0.198) 51(5.25,-5.526) 52(5.25,0.198) 53(5.751,-5.526) 54(5.751,0.198) 55(6.25,-5.526) 56(6.25,0.198) 57(6.75,-5.526) 58(6.75,0.198) 59(7.25,-5.526) 60(7.25,0.198)
C402H20
  custom 0.152x0.152 smd: 1(0,0.445) 2(0,-0.445)
C402H22
  custom 0.152x0.152 smd: 1(0,0.445) 2(0,-0.445)
C402H24
  custom 0.152x0.152 smd: 1(0,0.445) 2(0,-0.445)
C603
  custom 0.216x0.216 smd: 1(0,0.762) 2(0,-0.762)
C603H36
  custom 0.216x0.216 smd: 1(0,0.762) 2(0,-0.762)
C805H54
  rect 1.397x1.143 smd: 1(0,0.965) 2(0,-0.965)
C805H58
  rect 1.397x1.143 smd: 1(0,0.965) 2(0,-0.965)
C1206H71
  rect 1.651x1.27 smd: 1(0,1.397) 2(0,-1.397)
C4201WV0-2-12P
  round 2.184 hole 1.422: 1(-23.1,2.75) 2(-18.9,2.75) 3(-14.7,2.75) 4(-10.5,2.75) 5(-6.3,2.75) 6(-2.1,2.75) 7(2.1,2.75) 8(6.3,2.75) 9(10.5,2.75) 10(14.7,2.75) 11(18.9,2.75) 12(23.1,2.75) 13(-23.1,-2.75) 14(-18.9,-2.75) 15(-14.7,-2.75) 16(-10.5,-2.75) 17(-6.3,-2.75) 18(-2.1,-2.75) 19(2.1,-2.75) 20(6.3,-2.75) 21(10.5,-2.75) 22(14.7,-2.75) 23(18.9,-2.75) 24(23.1,-2.75)
CON2C-U
  custom 0.171x0.171 smd: 1(0,0.533) 2(0,-0.533)
DFN8G2-G1309-UH40
  rect 0.305x0.737 smd: 1(0.75,1.018) 2(0.25,1.018) 3(-0.25,1.018) 4(-0.75,1.018) 5(-0.75,-1.018) 6(-0.25,-1.018) 7(0.25,-1.018) 8(0.75,-1.018)
  rect 1.295x0.889 smd: 9(0,0)
DFN10G3-G265175H32
  rect 0.305x0.914 smd: 1(1,1.549) 2(0.5,1.549) 3(0,1.549) 4(-0.5,1.549) 5(-1,1.549) 6(-1,-1.549) 7(-0.5,-1.549) 8(0,-1.549) 9(0.5,-1.549) 10(1,-1.549)
  rect 2.642x1.753 smd: 11(0,0)
DFN10G2510H26
  rect 0.305x0.787 smd: 1(1,0.494) 5(-1,0.494) 6(-1,-0.494) 10(1,-0.494)
  rect 0.254x0.787 smd: 2(0.521,0.494) 4(-0.521,0.494) 7(-0.521,-0.494) 9(0.521,-0.494)
  rect 0.025x0.025 smd: 3(0,0.494)
  rect 0.406x1.753 smd: 8(0,-0.494)
DZ11AA1-H5W7-4F
  round 1.448 hole 1.041: 1(-4.326,-2) 2(-2.036,-2) 3(0.254,-2) 4(2.544,-2) 5(4.834,-2) 6(-5.471,0) 7(-3.181,0) 8(-0.892,0) 9(1.4,0) 10(3.689,0) 11(-4.326,2) 12(-2.036,2) 13(0.254,2) 14(2.544,2) 15(4.834,2)
  round 3.454 hole 3.048: 16(-12.496,0) 17(12.496,0)
ECAP-80D5H493
  rect 1.397x1.397 hole 0.991: 1(0,-1.016)
  round 1.397 hole 0.991: 2(0,1.016)
ECAP-100D6D3H237
  rect 1.397x1.397 hole 0.991: 1(0,-1.27)
  round 1.397 hole 0.991: 2(0,1.27)
ECAP-100D6D3H375
  rect 1.397x1.397 hole 0.991: 1(0,-1.27)
  round 1.397 hole 0.991: 2(0,1.27)
ECAP-100D6D3H473
  rect 1.397x1.397 hole 0.991: 1(0,-1.27)
  round 1.397 hole 0.991: 2(0,1.27)
ECAP-138D8-UH355
  rect 1.397x1.397 hole 0.991: 1(0,-1.75)
  round 1.397 hole 0.991: 2(0,1.75)
ECAP-138D8H512
  rect 1.397x1.397 hole 0.991: 1(0,-1.753)
  round 1.397 hole 0.991: 2(0,1.753)
G800W306018EU
  round 1.422 hole 1.016: 1(-1.27,0) 2(1.27,0)
G3168-18000101-00
  rect 0.305x2.591 smd: 1(4.5,0.755) 2(4,0.755) 3(3.5,0.755) 4(3,0.755) 5(2.5,0.755) 6(2,0.755) 7(1.5,0.755) 8(1,0.755) 9(0.5,0.755) 10(0,0.755) 11(-0.5,0.755) 12(-1,0.755) 13(-1.5,0.755) 14(-2,0.755) 15(-2.5,0.755) 16(-3,0.755) 17(-3.5,0.755) 18(-4,0.755) 19(-4.5,0.755)
  oval 1.626x3.429 hole 0.914x2.718: 20(7.25,0) 21(-7.25,0)
  oval 1.626x2.819 hole 0.914x2.108: 22(7.25,-5.96) 23(-7.25,-5.96)
GAP-CLOSE-PWR
  rect 0.66x0.762 smd: 1(-0.305,0) 2(0.305,0)
GENS315R158-8-F-A
  round 0.254 hole 4.013 unplated: (0,0)
  round 0.864 hole 0.508: 1(-0.634,3.189) 2(-2.703,1.806) 3(-3.189,-0.634) 4(-1.806,-2.703) 5(0.634,-3.189) 6(2.703,-1.806) 7(3.189,0.634) 8(1.806,2.703)
HF08040-M1
  round 0.254 hole 1.143 unplated: (-3.81,-2.16)
  round 1.549 hole 1.143: 1(3.81,0) 2(1.27,0) 3(-1.27,0) 4(-3.81,0)
HY-11H394
  round 1.778 hole 0.991: 1(-3.251,0) 2(3.251,0)
L402H24
  custom 0.14x0.14 smd: 1(0,0.445) 2(0,-0.445)
L603H38
  custom 0.216x0.216 smd: 1(0,0.762) 2(0,-0.762)
L1608-UH38
  custom 0.216x0.216 smd: 1(0,0.762) 2(0,-0.762)
L2012-4P-MH56
  rect 1.067x0.61 smd: 1(0.848,0.422) 2(-0.848,0.422) 3(-0.848,-0.422) 4(0.848,-0.422)
L3330-1230H95
  rect 3.251x1.778 smd: 1(0,1.135) 2(0,-1.135)
L125100-4P-1H37
  rect 0.762x0.432 smd: 1(0.625,0.341) 2(-0.625,0.341) 3(-0.625,-0.341) 4(0.625,-0.341)
L125100-4P-3H27
  rect 0.356x0.762 smd: 1(-0.275,-0.622) 2(0.275,-0.622) 3(0.275,0.622) 4(-0.275,0.622)
L201209H44
  rect 1.397x1.143 smd: 1(0,0.965) 2(0,-0.965)
LQFP48H63
  rect 0.305x1.524 smd: 1(2.75,4.242) 2(2.25,4.242) 3(1.75,4.242) 4(1.25,4.242) 5(0.751,4.242) 6(0.25,4.242) 7(-0.25,4.242) 8(-0.751,4.242) 9(-1.25,4.242) 10(-1.75,4.242) 11(-2.25,4.242) 12(-2.75,4.242) 25(-2.75,-4.242) 26(-2.25,-4.242) 27(-1.75,-4.242) 28(-1.25,-4.242) 29(-0.751,-4.242) 30(-0.25,-4.242) 31(0.25,-4.242) 32(0.751,-4.242) 33(1.25,-4.242) 34(1.75,-4.242) 35(2.25,-4.242) 36(2.75,-4.242)
  rect 1.524x0.305 smd: 13(-4.242,2.75) 14(-4.242,2.25) 15(-4.242,1.75) 16(-4.242,1.25) 17(-4.242,0.751) 18(-4.242,0.25) 19(-4.242,-0.25) 20(-4.242,-0.751) 21(-4.242,-1.25) 22(-4.242,-1.75) 23(-4.242,-2.25) 24(-4.242,-2.75) 37(4.242,-2.75) 38(4.242,-2.25) 39(4.242,-1.75) 40(4.242,-1.25) 41(4.242,-0.751) 42(4.242,-0.25) 43(4.242,0.25) 44(4.242,0.751) 45(4.242,1.25) 46(4.242,1.75) 47(4.242,2.25) 48(4.242,2.75)
LQFP64H63
  rect 0.203x1.524 smd: 1(3,4.242) 2(2.6,4.242) 3(2.2,4.242) 4(1.8,4.242) 5(1.4,4.242) 6(0.999,4.242) 7(0.599,4.242) 8(0.199,4.242) 9(-0.199,4.242) 10(-0.599,4.242) 11(-0.999,4.242) 12(-1.4,4.242) 13(-1.8,4.242) 14(-2.2,4.242) 15(-2.6,4.242) 16(-3,4.242) 33(-3,-4.242) 34(-2.6,-4.242) 35(-2.2,-4.242) 36(-1.8,-4.242) 37(-1.4,-4.242) 38(-0.999,-4.242) 39(-0.599,-4.242) 40(-0.199,-4.242) 41(0.199,-4.242) 42(0.599,-4.242) 43(0.999,-4.242) 44(1.4,-4.242) 45(1.8,-4.242) 46(2.2,-4.242) 47(2.6,-4.242) 48(3,-4.242)
  rect 1.524x0.203 smd: 17(-4.242,3) 18(-4.242,2.6) 19(-4.242,2.2) 20(-4.242,1.8) 21(-4.242,1.4) 22(-4.242,0.999) 23(-4.242,0.599) 24(-4.242,0.199) 25(-4.242,-0.199) 26(-4.242,-0.599) 27(-4.242,-0.999) 28(-4.242,-1.4) 29(-4.242,-1.8) 30(-4.242,-2.2) 31(-4.242,-2.6) 32(-4.242,-3) 49(4.242,-3) 50(4.242,-2.6) 51(4.242,-2.2) 52(4.242,-1.8) 53(4.242,-1.4) 54(4.242,-0.999) 55(4.242,-0.599) 56(4.242,-0.199) 57(4.242,0.199) 58(4.242,0.599) 59(4.242,0.999) 60(4.242,1.4) 61(4.242,1.8) 62(4.242,2.2) 63(4.242,2.6) 64(4.242,3)
NTC-402H24
  custom 0.152x0.152 smd: 1(0,0.445) 2(0,-0.445)
NTC-603H28
  custom 0.216x0.216 smd: 1(0,0.762) 2(0,-0.762)
POLYSW-3217-UH40
  rect 1.905x1.143 smd: 1(0,1.418) 2(0,-1.418)
POLYSW-4633-UH24
  rect 3.505x1.626 smd: 1(0,1.834) 2(0,-1.834)
PPAK-5PH45
  rect 0.762x1.524 smd: 1(-1.905,-3.81) 2(-0.635,-3.81) 3(0.635,-3.81) 4(1.905,-3.81)
  rect 5.283x5.08 smd: 5(0,0)
  rect 0.025x0.025 smd: 6(0.635,2.032) 7(-0.635,2.032) 8(-1.905,2.032)
QFN32J4-G2D8-3H40
  rect 0.203x0.508 smd: 1(1.4,1.886) 8(-1.4,1.886) 17(-1.4,-1.886) 24(1.4,-1.886)
  rect 0.203x0.533 smd: 2(1,1.886) 3(0.6,1.886) 4(0.2,1.886) 5(-0.2,1.886) 6(-0.6,1.886) 7(-1,1.886) 18(-1,-1.886) 19(-0.6,-1.886) 20(-0.2,-1.886) 21(0.2,-1.886) 22(0.6,-1.886) 23(1,-1.886)
  rect 0.508x0.203 smd: 9(-1.886,1.4) 16(-1.886,-1.4) 25(1.886,-1.4) 32(1.886,1.4)
  rect 0.533x0.203 smd: 10(-1.886,1) 11(-1.886,0.6) 12(-1.886,0.2) 13(-1.886,-0.2) 14(-1.886,-0.6) 15(-1.886,-1) 26(1.886,-1) 27(1.886,-0.6) 28(1.886,-0.2) 29(1.886,0.2) 30(1.886,0.6) 31(1.886,1)
  rect 2.794x2.794 smd: 33(0,0)
QFN32J4-G2D9-U1H36
  rect 0.203x0.864 smd: 1(1.4,2.085) 2(1,2.085) 3(0.6,2.085) 4(0.2,2.085) 5(-0.2,2.085) 6(-0.6,2.085) 7(-1,2.085) 8(-1.4,2.085) 17(-1.4,-2.085) 18(-1,-2.085) 19(-0.6,-2.085) 20(-0.2,-2.085) 21(0.2,-2.085) 22(0.6,-2.085) 23(1,-2.085) 24(1.4,-2.085)
  rect 0.864x0.203 smd: 9(-2.085,1.4) 10(-2.085,1) 11(-2.085,0.6) 12(-2.085,0.2) 13(-2.085,-0.2) 14(-2.085,-0.6) 15(-2.085,-1) 16(-2.085,-1.4) 25(2.085,-1.4) 26(2.085,-1) 27(2.085,-0.6) 28(2.085,-0.2) 29(2.085,0.2) 30(2.085,0.6) 31(2.085,1) 32(2.085,1.4)
  rect 2.692x2.692 smd: 33(0,0)
R402H14
  custom 0.14x0.14 smd: 1(0,0.445) 2(0,-0.445)
R402H16
  custom 0.14x0.14 smd: 1(0,0.445) 2(0,-0.445)
R603H22
  custom 0.216x0.216 smd: 1(0,0.762) 2(0,-0.762)
R805H24
  rect 1.397x1.143 smd: 1(0,0.965) 2(0,-0.965)
RT-D6-4D5-1010H375
  round 2.489 hole 1.727: 1(3,2.25) 2(-3,-2.25)
RT-D6D2-108108H426
  round 2.286 hole 1.524: 1(3.1,3.1) 2(-3.1,-3.1)
RT-D6D5-13H414-U
  round 1.88 hole 1.118: 1(-3.25,0) 2(3.25,0)
RU4-161A9WGF
  round 2.718 hole 2.311: G1(9.35,0) G2(-9.35,0) G3(6.57,-4.37) G4(-6.57,-4.37) G5(6.57,-10.05) G6(-6.57,-10.05) G7(9.35,-12.68) G8(-9.35,-12.68)
  round 1.321 hole 0.914: L1(7.2,5.47) L2(4.66,5.47) L3(-4.66,5.47) L4(-7.2,5.47) R1(5.715,0.1) R2(4.445,2.64) R3(3.175,0.1) R4(1.905,2.64) R5(0.635,0.1) R6(-0.635,2.64) R7(-1.905,0.1) R8(-3.175,2.64) R9(-4.445,0.1) R10(-5.715,2.64)
  round 1.346 hole 0.94: U1(-3.5,-7.339) U2(-0.999,-7.339) U3(0.999,-7.339) U4(3.5,-7.339) U5(-3.5,-4.719) U6(-0.999,-4.719) U7(0.999,-4.719) U8(3.5,-4.719)
SKT-USB12-157183
  round 1.346 hole 0.94: 1(-3.5,2.71) 2(-1,2.71) 3(1,2.71) 4(3.5,2.71) 5(-3.5,5.33) 6(-1,5.33) 7(1,5.33) 8(3.5,5.33)
  round 2.718 hole 2.311: 9(-6.57,0) 10(6.57,0) 11(-6.57,5.68) 12(6.57,5.68)
SKT-USB22-156174
  round 1.067 hole 0.711: 1(-3.5,2) 2(-1,2) 3(1,2) 4(3.5,2) 5(4,3.5) 6(2,3.5) 7(0,3.5) 8(-2,3.5) 9(-4,3.5) 10(-3.5,5.2) 11(-1,5.2) 12(1,5.2) 13(3.5,5.2) 14(4,6.7) 15(2,6.7) 16(0,6.7) 17(-2,6.7) 18(-4,6.7)
  round 2.718 hole 2.311: 19(-6.57,0) 20(6.57,0) 21(-6.57,5.68) 22(6.57,5.68)
SKTBGA1150R740611UH367NF
  round 0.254 hole 3.81 unplated: (-35.21,0) (25.81,18) (25.81,-18)
  round 0.508 smd: A4(-16.187,18.288) AU1(-18.931,-14.63) AU39(18.016,-15.545) AU40(18.931,-15.545) AV1(-18.931,-15.545) AV2(-18.016,-15.545) AV38(17.102,-16.459) AV39(18.016,-16.459) AW2(-18.016,-16.459) AW3(-17.102,-16.459) AW37(16.187,-17.374) AW38(17.102,-17.374) AY3(-17.102,-17.374) B3(-17.102,17.374) B4(-16.187,17.374) B37(16.187,16.459) B38(17.102,16.459) B39(18.016,16.459) C2(-18.016,16.459) C3(-17.102,16.459) C39(18.016,15.545) C40(18.931,15.545) D1(-18.931,15.545) D2(-18.016,15.545) D39(18.016,14.63) D40(18.931,14.63)
  oval 0.356x0.457 smd: A5(-15.273,18.288) A6(-14.359,18.288) A7(-13.444,18.288) A11(-9.787,18.288) A12(-8.872,18.288) A13(-7.958,18.288) A14(-7.043,18.288) A15(-6.129,18.288) A16(-5.215,18.288) A17(-4.3,18.288) A18(-3.386,18.288) AU18(-1.186,-15.545) AU19(-0.272,-15.545) AU20(0.643,-15.545) AU21(1.557,-15.545) AU22(2.471,-15.545) AU23(3.386,-15.545) AV16(-3.015,-16.459) AV17(-2.101,-16.459) AV18(-1.186,-16.459) AV19(-0.272,-16.459) AV20(0.643,-16.459) AV21(1.557,-16.459) AV22(2.471,-16.459) AV23(3.386,-16.459) AV24(4.3,-16.459) AV25(5.215,-16.459) AV26(6.129,-16.459) AV27(7.043,-16.459) AV28(7.958,-16.459) AV29(8.872,-16.459) AV30(9.787,-16.459) AV31(10.701,-16.459) AV32(11.615,-16.459) AV33(12.53,-16.459) AV34(13.444,-16.459) AV35(14.359,-16.459) AV36(15.273,-16.459) AW4(-16.187,-16.459) AW5(-15.273,-16.459) AW6(-14.359,-16.459) AW7(-13.444,-16.459) AW8(-12.53,-16.459) AW9(-11.615,-16.459) AW10(-10.701,-16.459) AW11(-7.587,-17.374) AW12(-6.673,-17.374) AW13(-5.758,-17.374) AW14(-4.844,-17.374) AW15(-3.929,-17.374) AW16(-3.015,-17.374) AW17(-2.101,-17.374) AW18(-1.186,-17.374) AW23(3.386,-17.374) AW24(4.3,-17.374) AW25(5.215,-17.374) AW26(6.129,-17.374) AW27(7.043,-17.374) AW28(7.958,-17.374) AW29(8.872,-17.374) AW30(9.787,-17.374) AW31(10.701,-17.374) AW32(11.615,-17.374) AW33(12.53,-17.374) AW34(13.444,-17.374) AW35(14.359,-17.374) AW36(15.273,-17.374) AY4(-16.187,-17.374) AY5(-15.273,-17.374) AY6(-14.359,-17.374) AY7(-13.444,-17.374) AY8(-12.53,-17.374) AY9(-11.615,-17.374) AY10(-10.701,-17.374) AY11(-7.587,-18.288) AY12(-6.673,-18.288) AY13(-5.758,-18.288) AY14(-4.844,-18.288) AY15(-3.929,-18.288) AY16(-3.015,-18.288) AY17(-2.101,-18.288) AY18(-1.186,-18.288) AY23(3.386,-18.288) AY24(4.3,-18.288) AY25(5.215,-18.288) AY26(6.129,-18.288) AY27(7.043,-18.288) AY28(7.958,-18.288) AY29(8.872,-18.288) AY30(9.787,-18.288) B5(-15.273,17.374) B6(-14.359,17.374) B7(-13.444,17.374) B8(-12.53,17.374) B9(-11.615,17.374) B10(-10.701,17.374) B11(-9.787,17.374) B12(-8.872,17.374) B13(-7.958,17.374) B14(-7.043,17.374) B15(-6.129,17.374) B16(-5.215,17.374) B17(-4.3,17.374) B18(-3.386,17.374) C8(-12.53,16.459) C9(-11.615,16.459) C10(-10.701,16.459) C11(-9.787,16.459) C19(-2.471,16.459) C20(-1.557,16.459) C21(-0.643,16.459) C22(0.272,16.459) D8(-12.53,15.545) D9(-11.615,15.545) D10(-10.701,15.545) D11(-9.787,15.545) D20(-1.557,15.545) D21(-0.643,15.545)
  round 0.429 smd: A23(1.186,18.288) A24(2.101,18.288) A25(3.015,18.288) A26(3.929,18.288) A27(4.844,18.288) A28(5.758,18.288) A29(6.673,18.288) A30(7.587,18.288) AA5(-15.273,0) AA6(-14.359,0) AA7(-13.444,0) AA33(12.53,-0.914) AA34(13.444,-0.914) AA35(14.359,-0.914) AA36(15.273,-0.914) AB5(-15.273,-0.914) AB6(-14.359,-0.914) AB7(-13.444,-0.914) AB33(12.53,-1.829) AB34(13.444,-1.829) AB35(14.359,-1.829) AB36(15.273,-1.829) AB39(18.016,-1.829) AB40(18.931,-1.829) AC5(-15.273,-1.829) AC6(-14.359,-1.829) AC7(-13.444,-1.829) AC33(12.53,-2.743) AC34(13.444,-2.743) AC35(14.359,-2.743) AC36(15.273,-2.743) AC37(16.187,-2.743) AC38(17.102,-2.743) AD3(-17.102,-2.743) AD4(-16.187,-2.743) AD5(-15.273,-2.743) AD6(-14.359,-2.743) AD7(-13.444,-2.743) AD33(12.53,-3.658) AD34(13.444,-3.658) AD35(14.359,-3.658) AD36(15.273,-3.658) AD37(16.187,-3.658) AD38(17.102,-3.658) AE3(-17.102,-3.658) AE4(-16.187,-3.658) AE5(-15.273,-3.658) AE6(-14.359,-3.658) AE7(-13.444,-3.658) AE33(12.53,-4.572) AE34(13.444,-4.572) AE35(14.359,-4.572) AE36(15.273,-4.572) AE37(16.187,-4.572) AE38(17.102,-4.572) AF3(-17.102,-4.572) AF4(-16.187,-4.572) AF5(-15.273,-4.572) AF6(-14.359,-4.572) AF7(-13.444,-4.572) AF33(12.53,-5.486) AF34(13.444,-5.486) AF35(14.359,-5.486) AF36(15.273,-5.486) AF37(16.187,-5.486) AF38(17.102,-5.486) AG3(-17.102,-5.486) AG4(-16.187,-5.486) AG5(-15.273,-5.486) AG6(-14.359,-5.486) AG7(-13.444,-5.486) AG8(-12.53,-5.486) AG33(12.53,-6.401) AG34(13.444,-6.401) AG35(14.359,-6.401) AG36(15.273,-6.401) AG37(16.187,-6.401) AG38(17.102,-6.401) AH3(-17.102,-6.401) AH4(-16.187,-6.401) AH5(-15.273,-6.401) AH6(-14.359,-6.401) AH7(-13.444,-6.401) AH8(-12.53,-6.401) AH33(12.53,-7.315) AH34(13.444,-7.315) AH35(14.359,-7.315) AH36(15.273,-7.315) AH37(16.187,-7.315) AH38(17.102,-7.315) AJ3(-17.102,-7.315) AJ4(-16.187,-7.315) AJ5(-15.273,-7.315) AJ6(-14.359,-7.315) AJ7(-13.444,-7.315) AJ8(-12.53,-7.315) AJ9(-11.615,-7.315) AJ11(-7.587,-8.23) AJ12(-6.673,-8.23) AJ13(-5.758,-8.23) AJ14(-4.844,-8.23) AJ15(-3.929,-8.23) AJ16(-3.015,-8.23) AJ17(-2.101,-8.23) AJ18(-1.186,-8.23) AJ19(-0.272,-8.23) AJ20(0.643,-8.23) AJ21(1.557,-8.23) AJ22(2.471,-8.23) AJ23(3.386,-8.23) AJ24(4.3,-8.23) AJ25(5.215,-8.23) AJ26(6.129,-8.23) AJ27(7.043,-8.23) AJ28(7.958,-8.23) AJ29(8.872,-8.23) AJ30(9.787,-8.23) AJ31(10.701,-8.23) AJ32(11.615,-8.23) AJ33(12.53,-8.23) AJ34(13.444,-8.23) AJ35(14.359,-8.23) AJ36(15.273,-8.23) AJ37(16.187,-8.23) AJ38(17.102,-8.23) AK3(-17.102,-8.23) AK4(-16.187,-8.23) AK5(-15.273,-8.23) AK6(-14.359,-8.23) AK7(-13.444,-8.23) AK8(-12.53,-8.23) AK9(-11.615,-8.23) AK10(-10.701,-8.23) AK11(-7.587,-9.144) AK12(-6.673,-9.144) AK13(-5.758,-9.144) AK14(-4.844,-9.144) AK15(-3.929,-9.144) AK16(-3.015,-9.144) AK17(-2.101,-9.144) AK18(-1.186,-9.144) AK19(-0.272,-9.144) AK20(0.643,-9.144) AK21(1.557,-9.144) AK22(2.471,-9.144) AK23(3.386,-9.144) AK24(4.3,-9.144) AK25(5.215,-9.144) AK26(6.129,-9.144) AK27(7.043,-9.144) AK28(7.958,-9.144) AK29(8.872,-9.144) AK30(9.787,-9.144) AK31(10.701,-9.144) AK32(11.615,-9.144) AK33(12.53,-9.144) AK34(13.444,-9.144) AK35(14.359,-9.144) AK36(15.273,-9.144) AK37(16.187,-9.144) AK38(17.102,-9.144) AL3(-17.102,-9.144) AL4(-16.187,-9.144) AL5(-15.273,-9.144) AL6(-14.359,-9.144) AL7(-13.444,-9.144) AL8(-12.53,-9.144) AL9(-11.615,-9.144) AL10(-10.701,-9.144) AL11(-7.587,-10.058) AL12(-6.673,-10.058) AL13(-5.758,-10.058) AL14(-4.844,-10.058) AL15(-3.929,-10.058) AL16(-3.015,-10.058) AL17(-2.101,-10.058) AL18(-1.186,-10.058) AL19(-0.272,-10.058) AL20(0.643,-10.058) AL21(1.557,-10.058) AL22(2.471,-10.058) AL23(3.386,-10.058) AL24(4.3,-10.058) AL25(5.215,-10.058) AL26(6.129,-10.058) AL27(7.043,-10.058) AL28(7.958,-10.058) AL29(8.872,-10.058) AL30(9.787,-10.058) AL31(10.701,-10.058) AL32(11.615,-10.058) AL33(12.53,-10.058) AL34(13.444,-10.058) AL35(14.359,-10.058) AL36(15.273,-10.058) AL37(16.187,-10.058) AL38(17.102,-10.058) AM3(-17.102,-10.058) AM4(-16.187,-10.058) AM5(-15.273,-10.058) AM6(-14.359,-10.058) AM7(-13.444,-10.058) AM8(-12.53,-10.058) AM9(-11.615,-10.058) AM10(-10.701,-10.058) AM11(-7.587,-10.973) AM12(-6.673,-10.973) AM13(-5.758,-10.973) AM14(-4.844,-10.973) AM15(-3.929,-10.973) AM16(-3.015,-10.973) AM17(-2.101,-10.973) AM18(-1.186,-10.973) AM19(-0.272,-10.973) AM20(0.643,-10.973) AM21(1.557,-10.973) AM22(2.471,-10.973) AM23(3.386,-10.973) AM24(4.3,-10.973) AM25(5.215,-10.973) AM26(6.129,-10.973) AM27(7.043,-10.973) AM28(7.958,-10.973) AM29(8.872,-10.973) AM30(9.787,-10.973) AM31(10.701,-10.973) AM32(11.615,-10.973) AM33(12.53,-10.973) AM34(13.444,-10.973) AM35(14.359,-10.973) AM36(15.273,-10.973) AM37(16.187,-10.973) AM38(17.102,-10.973) AN3(-17.102,-10.973) AN4(-16.187,-10.973) AN5(-15.273,-10.973) AN6(-14.359,-10.973) AN7(-13.444,-10.973) AN8(-12.53,-10.973) AN9(-11.615,-10.973) AN10(-10.701,-10.973) AN11(-7.587,-11.887) AN12(-6.673,-11.887) AN13(-5.758,-11.887) AN14(-4.844,-11.887) AN15(-3.929,-11.887) AN16(-3.015,-11.887) AN17(-2.101,-11.887) AN18(-1.186,-11.887) AN19(-0.272,-11.887) AN20(0.643,-11.887) AN21(1.557,-11.887) AN22(2.471,-11.887) AN23(3.386,-11.887) AN24(4.3,-11.887) AN25(5.215,-11.887) AN26(6.129,-11.887) AN27(7.043,-11.887) AN28(7.958,-11.887) AN29(8.872,-11.887) AN30(9.787,-11.887) AN31(10.701,-11.887) AN32(11.615,-11.887) AN33(12.53,-11.887) AN34(13.444,-11.887) AN35(14.359,-11.887) AN36(15.273,-11.887) AN37(16.187,-11.887) AN38(17.102,-11.887) AP3(-17.102,-11.887) AP4(-16.187,-11.887) AP5(-15.273,-11.887) AP6(-14.359,-11.887) AP7(-13.444,-11.887) AP8(-12.53,-11.887) AP9(-11.615,-11.887) AP10(-10.701,-11.887) AP11(-7.587,-12.802) AP12(-6.673,-12.802) AP13(-5.758,-12.802) AP14(-4.844,-12.802) AP15(-3.929,-12.802) AP16(-3.015,-12.802) AP17(-2.101,-12.802) AP18(-1.186,-12.802) AP19(-0.272,-12.802) AP20(0.643,-12.802) AP21(1.557,-12.802) AP22(2.471,-12.802) AP23(3.386,-12.802) AP24(4.3,-12.802) AP25(5.215,-12.802) AP26(6.129,-12.802) AP27(7.043,-12.802) AP28(7.958,-12.802) AP29(8.872,-12.802) AP30(9.787,-12.802) AP31(10.701,-12.802) AP32(11.615,-12.802) AP33(12.53,-12.802) AP34(13.444,-12.802) AP35(14.359,-12.802) AP36(15.273,-12.802) AP37(16.187,-12.802) AP38(17.102,-12.802) AR3(-17.102,-12.802) AR4(-16.187,-12.802) AR5(-15.273,-12.802) AR6(-14.359,-12.802) AR7(-13.444,-12.802) AR8(-12.53,-12.802) AR9(-11.615,-12.802) AR10(-10.701,-12.802) AR11(-7.587,-13.716) AR12(-6.673,-13.716) AR13(-5.758,-13.716) AR14(-4.844,-13.716) AR15(-3.929,-13.716) AR16(-3.015,-13.716) AR17(-2.101,-13.716) AR18(-1.186,-13.716) AR19(-0.272,-13.716) AR20(0.643,-13.716) AR21(1.557,-13.716) AR22(2.471,-13.716) AR23(3.386,-13.716) AR24(4.3,-13.716) AR25(5.215,-13.716) AR26(6.129,-13.716) AR27(7.043,-13.716) AR28(7.958,-13.716) AR29(8.872,-13.716) AR30(9.787,-13.716) AR31(10.701,-13.716) AR32(11.615,-13.716) AR33(12.53,-13.716) AR34(13.444,-13.716) AR35(14.359,-13.716) AR36(15.273,-13.716) AR37(16.187,-13.716) AR38(17.102,-13.716) AT3(-17.102,-13.716) AT4(-16.187,-13.716) AT5(-15.273,-13.716) AT6(-14.359,-13.716) AT7(-13.444,-13.716) AT8(-12.53,-13.716) AT9(-11.615,-13.716) AT10(-10.701,-13.716) AT11(-7.587,-14.63) AT12(-6.673,-14.63) AT13(-5.758,-14.63) AT14(-4.844,-14.63) AT15(-3.929,-14.63) AT16(-3.015,-14.63) AT17(-2.101,-14.63) AT18(-1.186,-14.63) AT19(-0.272,-14.63) AT20(0.643,-14.63) AT21(1.557,-14.63) AT22(2.471,-14.63) AT23(3.386,-14.63) AT24(4.3,-14.63) AT25(5.215,-14.63) AT26(6.129,-14.63) AT27(7.043,-14.63) AT28(7.958,-14.63) AT29(8.872,-14.63) AT30(9.787,-14.63) AT31(10.701,-14.63) AT32(11.615,-14.63) AT33(12.53,-14.63) AT34(13.444,-14.63) AT35(14.359,-14.63) AT36(15.273,-14.63) AT37(16.187,-14.63) AT38(17.102,-14.63) AU3(-17.102,-14.63) AU4(-16.187,-14.63) AU5(-15.273,-14.63) AU6(-14.359,-14.63) AU7(-13.444,-14.63) AU8(-12.53,-14.63) AU9(-11.615,-14.63) AU10(-10.701,-14.63) AU11(-7.587,-15.545) AU12(-6.673,-15.545) AU13(-5.758,-15.545) AU14(-4.844,-15.545) AU15(-3.929,-15.545) AU16(-3.015,-15.545) AU17(-2.101,-15.545) AU24(4.3,-15.545) AU25(5.215,-15.545) AU26(6.129,-15.545) AU27(7.043,-15.545) AU28(7.958,-15.545) AU29(8.872,-15.545) AU30(9.787,-15.545) AU31(10.701,-15.545) AU32(11.615,-15.545) AU33(12.53,-15.545) AU34(13.444,-15.545) AU35(14.359,-15.545) AU36(15.273,-15.545) AU37(16.187,-15.545) AU38(17.102,-15.545) AV3(-17.102,-15.545) AV4(-16.187,-15.545) AV5(-15.273,-15.545) AV6(-14.359,-15.545) AV7(-13.444,-15.545) AV8(-12.53,-15.545) AV9(-11.615,-15.545) AV10(-10.701,-15.545) AV11(-7.587,-16.459) AV12(-6.673,-16.459) AV13(-5.758,-16.459) AV14(-4.844,-16.459) AV15(-3.929,-16.459) AV37(16.187,-16.459) B23(1.186,17.374) B24(2.101,17.374) B25(3.015,17.374) B26(3.929,17.374) B27(4.844,17.374) B28(5.758,17.374) B29(6.673,17.374) B30(7.587,17.374) B31(10.701,16.459) B32(11.615,16.459) B33(12.53,16.459) B34(13.444,16.459) B35(14.359,16.459) B36(15.273,16.459) C4(-16.187,16.459) C5(-15.273,16.459) C6(-14.359,16.459) C7(-13.444,16.459) C12(-8.872,16.459) C13(-7.958,16.459) C14(-7.043,16.459) C15(-6.129,16.459) C16(-5.215,16.459) C17(-4.3,16.459) C18(-3.386,16.459) C23(1.186,16.459) C24(2.101,16.459) C25(3.015,16.459) C26(3.929,16.459) C27(4.844,16.459) C28(5.758,16.459) C29(6.673,16.459) C30(7.587,16.459) C31(10.701,15.545) C32(11.615,15.545) C33(12.53,15.545) C34(13.444,15.545) C35(14.359,15.545) C36(15.273,15.545) C37(16.187,15.545) C38(17.102,15.545) D3(-17.102,15.545) D4(-16.187,15.545) D5(-15.273,15.545) D6(-14.359,15.545) D7(-13.444,15.545) D12(-8.872,15.545) D13(-7.958,15.545) D14(-7.043,15.545) D15(-6.129,15.545) D16(-5.215,15.545) D17(-4.3,15.545) D18(-3.386,15.545) D19(-2.471,15.545) D22(0.272,15.545) D23(1.186,15.545) D24(2.101,15.545) D25(3.015,15.545) D26(3.929,15.545) D27(4.844,15.545) D28(5.758,15.545) D29(6.673,15.545) D30(7.587,15.545) D31(10.701,14.63) D32(11.615,14.63) D33(12.53,14.63) D34(13.444,14.63) D35(14.359,14.63) D36(15.273,14.63) D37(16.187,14.63) D38(17.102,14.63) E4(-16.187,14.63) E5(-15.273,14.63) E6(-14.359,14.63) E7(-13.444,14.63) E8(-12.53,14.63) E9(-11.615,14.63) E10(-10.701,14.63) E11(-9.787,14.63) E12(-8.872,14.63) E13(-7.958,14.63) E14(-7.043,14.63) E15(-6.129,14.63) E16(-5.215,14.63) E17(-4.3,14.63) E18(-3.386,14.63) E19(-2.471,14.63) E20(-1.557,14.63) E21(-0.643,14.63) E22(0.272,14.63) E23(1.186,14.63) E24(2.101,14.63) E25(3.015,14.63) E26(3.929,14.63) E27(4.844,14.63) E28(5.758,14.63) E29(6.673,14.63) E30(7.587,14.63) E31(10.701,13.716) E32(11.615,13.716) E33(12.53,13.716) E34(13.444,13.716) E35(14.359,13.716) E36(15.273,13.716) E37(16.187,13.716) E38(17.102,13.716) F4(-16.187,13.716) F5(-15.273,13.716) F6(-14.359,13.716) F7(-13.444,13.716) F8(-12.53,13.716) F9(-11.615,13.716) F10(-10.701,13.716) F11(-9.787,13.716) F12(-8.872,13.716) F13(-7.958,13.716) F14(-7.043,13.716) F15(-6.129,13.716) F16(-5.215,13.716) F17(-4.3,13.716) F18(-3.386,13.716) F19(-2.471,13.716) F20(-1.557,13.716) F21(-0.643,13.716) F22(0.272,13.716) F23(1.186,13.716) F24(2.101,13.716) F25(3.015,13.716) F26(3.929,13.716) F27(4.844,13.716) F28(5.758,13.716) F29(6.673,13.716) F30(7.587,13.716) F31(10.701,12.802) F32(11.615,12.802) F33(12.53,12.802) F34(13.444,12.802) F35(14.359,12.802) F36(15.273,12.802) F37(16.187,12.802) F38(17.102,12.802) F39(18.016,12.802) G4(-16.187,12.802) G5(-15.273,12.802) G6(-14.359,12.802) G7(-13.444,12.802) G8(-12.53,12.802) G9(-11.615,12.802) G10(-10.701,12.802) G11(-9.787,12.802) G12(-8.872,12.802) G13(-7.958,12.802) G14(-7.043,12.802) G15(-6.129,12.802) G16(-5.215,12.802) G17(-4.3,12.802) G18(-3.386,12.802) G19(-2.471,12.802) G20(-1.557,12.802) G21(-0.643,12.802) G22(0.272,12.802) G23(1.186,12.802) G24(2.101,12.802) G25(3.015,12.802) G26(3.929,12.802) G27(4.844,12.802) G28(5.758,12.802) G29(6.673,12.802) G30(7.587,12.802) G31(10.701,11.887) G32(11.615,11.887) G33(12.53,11.887) G34(13.444,11.887) G35(14.359,11.887) G36(15.273,11.887) G37(16.187,11.887) G38(17.102,11.887) G39(18.016,11.887) G40(18.931,11.887) H4(-16.187,11.887) H5(-15.273,11.887) H6(-14.359,11.887) H7(-13.444,11.887) H8(-12.53,11.887) H9(-11.615,11.887) H10(-10.701,11.887) H11(-9.787,11.887) H12(-8.872,11.887) H13(-7.958,11.887) H14(-7.043,11.887) H15(-6.129,11.887) H16(-5.215,11.887) H17(-4.3,11.887) H18(-3.386,11.887) H19(-2.471,11.887) H20(-1.557,11.887) H21(-0.643,11.887) H22(0.272,11.887) H23(1.186,11.887) H24(2.101,11.887) H25(3.015,11.887) H26(3.929,11.887) H27(4.844,11.887) H28(5.758,11.887) H29(6.673,11.887) H30(7.587,11.887) H31(10.701,10.973) H32(11.615,10.973) H33(12.53,10.973) H34(13.444,10.973) H35(14.359,10.973) H36(15.273,10.973) H37(16.187,10.973) H38(17.102,10.973) H39(18.016,10.973) H40(18.931,10.973) J4(-16.187,10.973) J5(-15.273,10.973) J6(-14.359,10.973) J7(-13.444,10.973) J8(-12.53,10.973) J9(-11.615,10.973) J10(-10.701,10.973) J11(-9.787,10.973) J12(-8.872,10.973) J13(-7.958,10.973) J14(-7.043,10.973) J15(-6.129,10.973) J16(-5.215,10.973) J17(-4.3,10.973) J18(-3.386,10.973) J19(-2.471,10.973) J20(-1.557,10.973) J21(-0.643,10.973) J22(0.272,10.973) J23(1.186,10.973) J24(2.101,10.973) J25(3.015,10.973) J26(3.929,10.973) J27(4.844,10.973) J28(5.758,10.973) J29(6.673,10.973) J30(7.587,10.973) J31(10.701,10.058) J32(11.615,10.058) J33(12.53,10.058) J34(13.444,10.058) J35(14.359,10.058) J36(15.273,10.058) J37(16.187,10.058) J38(17.102,10.058) J39(18.016,10.058) J40(18.931,10.058) K4(-16.187,10.058) K5(-15.273,10.058) K6(-14.359,10.058) K7(-13.444,10.058) K8(-12.53,10.058) K9(-11.615,10.058) K10(-10.701,10.058) K11(-9.787,10.058) K12(-8.872,10.058) K13(-7.958,10.058) K14(-7.043,10.058) K15(-6.129,10.058) K16(-5.215,10.058) K17(-4.3,10.058) K18(-3.386,10.058) K19(-2.471,10.058) K20(-1.557,10.058) K21(-0.643,10.058) K22(0.272,10.058) K23(1.186,10.058) K24(2.101,10.058) K25(3.015,10.058) K26(3.929,10.058) K27(4.844,10.058) K28(5.758,10.058) K29(6.673,10.058) K30(7.587,10.058) K31(10.701,9.144) K32(11.615,9.144) K33(12.53,9.144) K34(13.444,9.144) K35(14.359,9.144) K36(15.273,9.144) K37(16.187,9.144) K38(17.102,9.144) K39(18.016,9.144) L4(-16.187,9.144) L5(-15.273,9.144) L6(-14.359,9.144) L7(-13.444,9.144) L8(-12.53,9.144) L9(-11.615,9.144) L10(-10.701,9.144) L11(-9.787,9.144) L12(-8.872,9.144) L13(-7.958,9.144) L14(-7.043,9.144) L15(-6.129,9.144) L16(-5.215,9.144) L17(-4.3,9.144) L18(-3.386,9.144) L19(-2.471,9.144) L20(-1.557,9.144) L21(-0.643,9.144) L22(0.272,9.144) L23(1.186,9.144) L24(2.101,9.144) L25(3.015,9.144) L26(3.929,9.144) L27(4.844,9.144) L28(5.758,9.144) L29(6.673,9.144) L30(7.587,9.144) L31(10.701,8.23) L32(11.615,8.23) L33(12.53,8.23) L34(13.444,8.23) L35(14.359,8.23) L36(15.273,8.23) L37(16.187,8.23) L38(17.102,8.23) L39(18.016,8.23) M4(-16.187,8.23) M5(-15.273,8.23) M6(-14.359,8.23) M7(-13.444,8.23) M8(-12.53,8.23) M9(-11.615,8.23) M10(-10.701,8.23) M11(-9.787,8.23) M12(-8.872,8.23) M13(-7.958,8.23) M14(-7.043,8.23) M15(-6.129,8.23) M16(-5.215,8.23) M17(-4.3,8.23) M18(-3.386,8.23) M19(-2.471,8.23) M20(-1.557,8.23) M21(-0.643,8.23) M22(0.272,8.23) M23(1.186,8.23) M24(2.101,8.23) M25(3.015,8.23) M26(3.929,8.23) M27(4.844,8.23) M28(5.758,8.23) M29(6.673,8.23) M30(7.587,8.23) M32(11.615,7.315) M33(12.53,7.315) M34(13.444,7.315) M35(14.359,7.315) M36(15.273,7.315) M37(16.187,7.315) M38(17.102,7.315) M39(18.016,7.315) N4(-16.187,7.315) N5(-15.273,7.315) N6(-14.359,7.315) N7(-13.444,7.315) N8(-12.53,7.315) N33(12.53,6.401) N34(13.444,6.401) N35(14.359,6.401) N36(15.273,6.401) N37(16.187,6.401) N38(17.102,6.401) N39(18.016,6.401) P4(-16.187,6.401) P5(-15.273,6.401) P6(-14.359,6.401) P7(-13.444,6.401) P8(-12.53,6.401) P33(12.53,5.486) P34(13.444,5.486) P35(14.359,5.486) P36(15.273,5.486) P37(16.187,5.486) P38(17.102,5.486) P39(18.016,5.486) R4(-16.187,5.486) R5(-15.273,5.486) R6(-14.359,5.486) R7(-13.444,5.486) R8(-12.53,5.486) R33(12.53,4.572) R34(13.444,4.572) R35(14.359,4.572) R36(15.273,4.572) R37(16.187,4.572) R38(17.102,4.572) R39(18.016,4.572) T4(-16.187,4.572) T5(-15.273,4.572) T6(-14.359,4.572) T7(-13.444,4.572) T8(-12.53,4.572) T33(12.53,3.658) T34(13.444,3.658) T35(14.359,3.658) T36(15.273,3.658) T37(16.187,3.658) T38(17.102,3.658) T39(18.016,3.658) U6(-14.359,3.658) U7(-13.444,3.658) U33(12.53,2.743) U34(13.444,2.743) U35(14.359,2.743) U36(15.273,2.743) U37(16.187,2.743) U38(17.102,2.743) V6(-14.359,2.743) V7(-13.444,2.743) V33(12.53,1.829) V34(13.444,1.829) V35(14.359,1.829) V36(15.273,1.829) V37(16.187,1.829) V38(17.102,1.829) W5(-15.273,1.829) W6(-14.359,1.829) W7(-13.444,1.829) W33(12.53,0.914) W34(13.444,0.914) W35(14.359,0.914) W36(15.273,0.914) W37(16.187,0.914) W38(17.102,0.914) Y5(-15.273,0.914) Y6(-14.359,0.914) Y7(-13.444,0.914) Y33(12.53,0) Y34(13.444,0) Y35(14.359,0) Y36(15.273,0) Y37(16.187,0)
  oval 0.457x0.356 smd: AA3(-17.102,0) AA4(-16.187,0) AA8(-12.53,0) AA37(16.187,-0.914) AA38(17.102,-0.914) AB3(-17.102,-0.914) AB4(-16.187,-0.914) AB8(-12.53,-0.914) AB37(16.187,-1.829) AB38(17.102,-1.829) AC1(-18.931,-1.829) AC2(-18.016,-1.829) AC3(-17.102,-1.829) AC4(-16.187,-1.829) AC8(-12.53,-1.829) AC39(18.016,-2.743) AC40(18.931,-2.743) AD1(-18.931,-2.743) AD2(-18.016,-2.743) AD8(-12.53,-2.743) AD39(18.016,-3.658) AD40(18.931,-3.658) AE1(-18.931,-3.658) AE2(-18.016,-3.658) AE8(-12.53,-3.658) AE39(18.016,-4.572) AE40(18.931,-4.572) AF1(-18.931,-4.572) AF2(-18.016,-4.572) AF8(-12.53,-4.572) AF39(18.016,-5.486) AF40(18.931,-5.486) AG1(-18.931,-5.486) AG2(-18.016,-5.486) AG39(18.016,-6.401) AG40(18.931,-6.401) AH1(-18.931,-6.401) AH2(-18.016,-6.401) AH39(18.016,-7.315) AH40(18.931,-7.315) AJ1(-18.931,-7.315) AJ2(-18.016,-7.315) AJ39(18.016,-8.23) AJ40(18.931,-8.23) AK1(-18.931,-8.23) AK2(-18.016,-8.23) AK39(18.016,-9.144) AK40(18.931,-9.144) AL1(-18.931,-9.144) AL2(-18.016,-9.144) AL39(18.016,-10.058) AL40(18.931,-10.058) AM1(-18.931,-10.058) AM2(-18.016,-10.058) AM39(18.016,-10.973) AM40(18.931,-10.973) AN1(-18.931,-10.973) AN2(-18.016,-10.973) AN39(18.016,-11.887) AN40(18.931,-11.887) AP1(-18.931,-11.887) AP2(-18.016,-11.887) AP39(18.016,-12.802) AP40(18.931,-12.802) AR1(-18.931,-12.802) AR2(-18.016,-12.802) AR39(18.016,-13.716) AR40(18.931,-13.716) AT1(-18.931,-13.716) AT2(-18.016,-13.716) AT39(18.016,-14.63) AT40(18.931,-14.63) AU2(-18.016,-14.63) E1(-18.931,14.63) E2(-18.016,14.63) E3(-17.102,14.63) E39(18.016,13.716) E40(18.931,13.716) F1(-18.931,13.716) F2(-18.016,13.716) F3(-17.102,13.716) F40(18.931,12.802) G1(-18.931,12.802) G2(-18.016,12.802) G3(-17.102,12.802) H1(-18.931,11.887) H2(-18.016,11.887) H3(-17.102,11.887) J1(-18.931,10.973) J2(-18.016,10.973) J3(-17.102,10.973) K1(-18.931,10.058) K2(-18.016,10.058) K3(-17.102,10.058) K40(18.931,9.144) L1(-18.931,9.144) L2(-18.016,9.144) L3(-17.102,9.144) L40(18.931,8.23) M1(-18.931,8.23) M2(-18.016,8.23) M3(-17.102,8.23) M40(18.931,7.315) N1(-18.931,7.315) N2(-18.016,7.315) N3(-17.102,7.315) N40(18.931,6.401) P1(-18.931,6.401) P2(-18.016,6.401) P3(-17.102,6.401) P40(18.931,5.486) R1(-18.931,5.486) R2(-18.016,5.486) R3(-17.102,5.486) R40(18.931,4.572) T1(-18.931,4.572) T2(-18.016,4.572) T3(-17.102,4.572) T40(18.931,3.658) U1(-18.931,3.658) U2(-18.016,3.658) U3(-17.102,3.658) U4(-16.187,3.658) U5(-15.273,3.658) U8(-12.53,3.658) U39(18.016,2.743) U40(18.931,2.743) V1(-18.931,2.743) V2(-18.016,2.743) V3(-17.102,2.743) V4(-16.187,2.743) V5(-15.273,2.743) V8(-12.53,2.743) V39(18.016,1.829) V40(18.931,1.829) W1(-18.931,1.829) W2(-18.016,1.829) W3(-17.102,1.829) W4(-16.187,1.829) W8(-12.53,1.829) Y3(-17.102,0.914) Y4(-16.187,0.914) Y8(-12.53,0.914) Y38(17.102,0)
